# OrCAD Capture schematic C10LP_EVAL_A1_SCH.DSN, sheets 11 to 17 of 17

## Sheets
11 11. Ethernet: size B
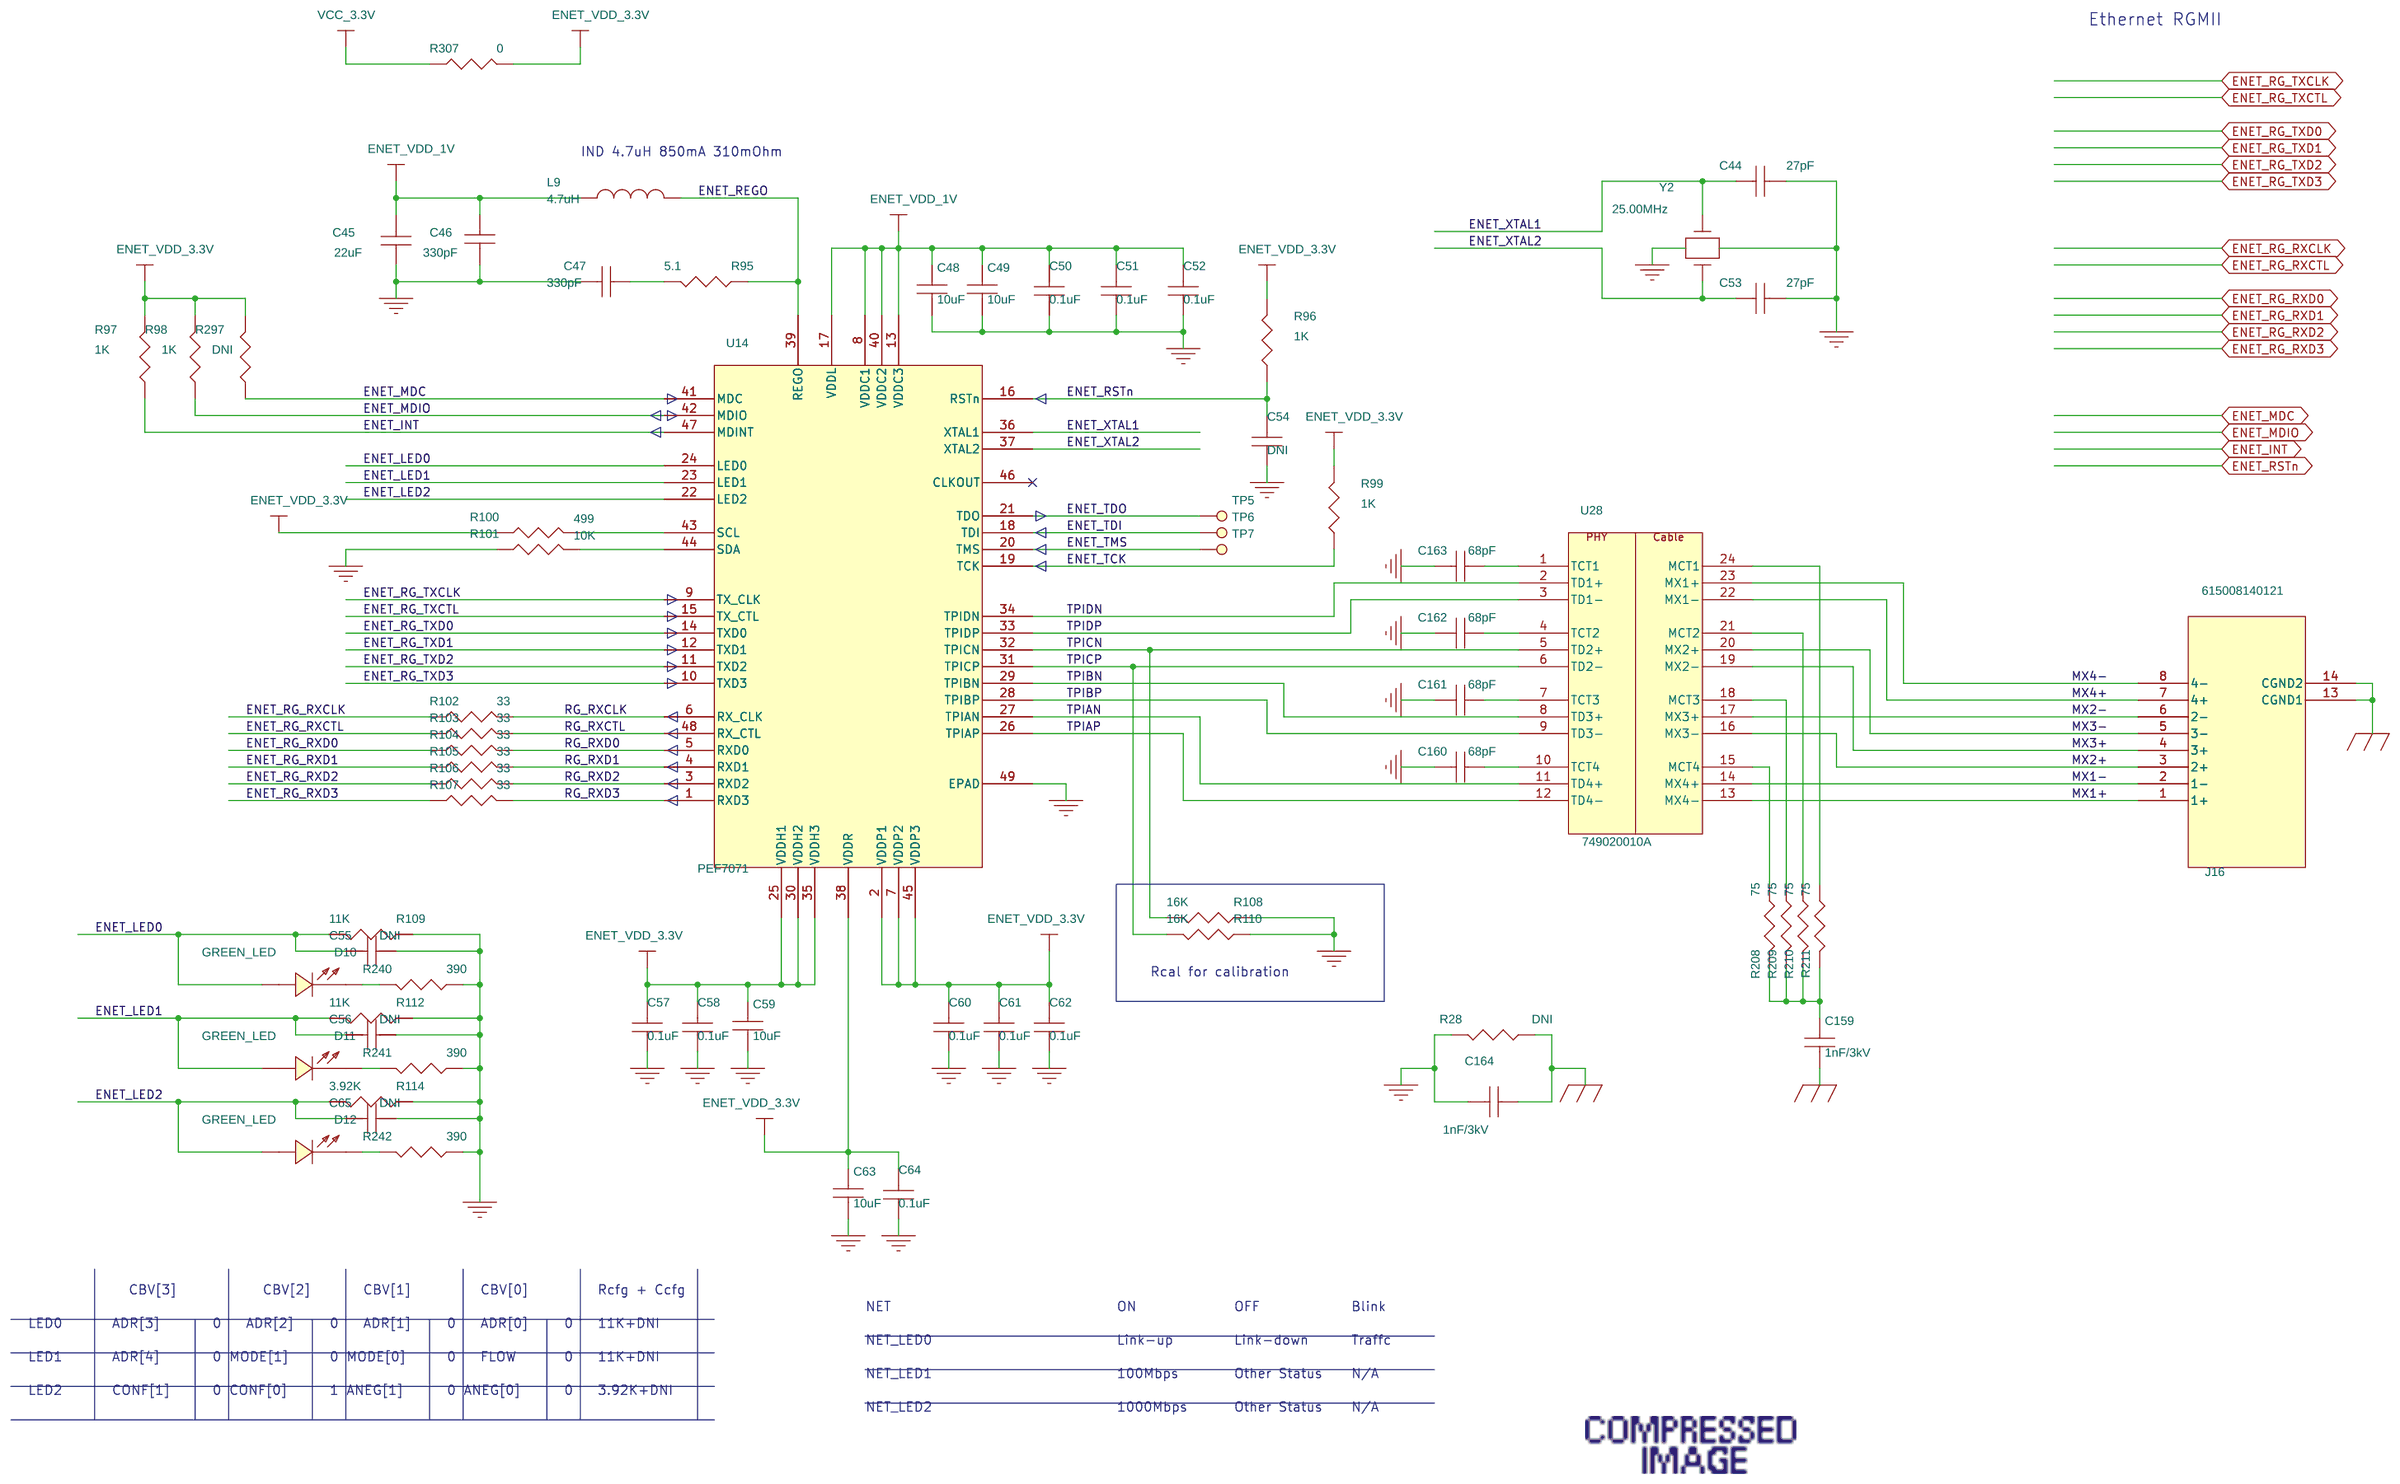
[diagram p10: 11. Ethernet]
12 12. Arduino Header: size B
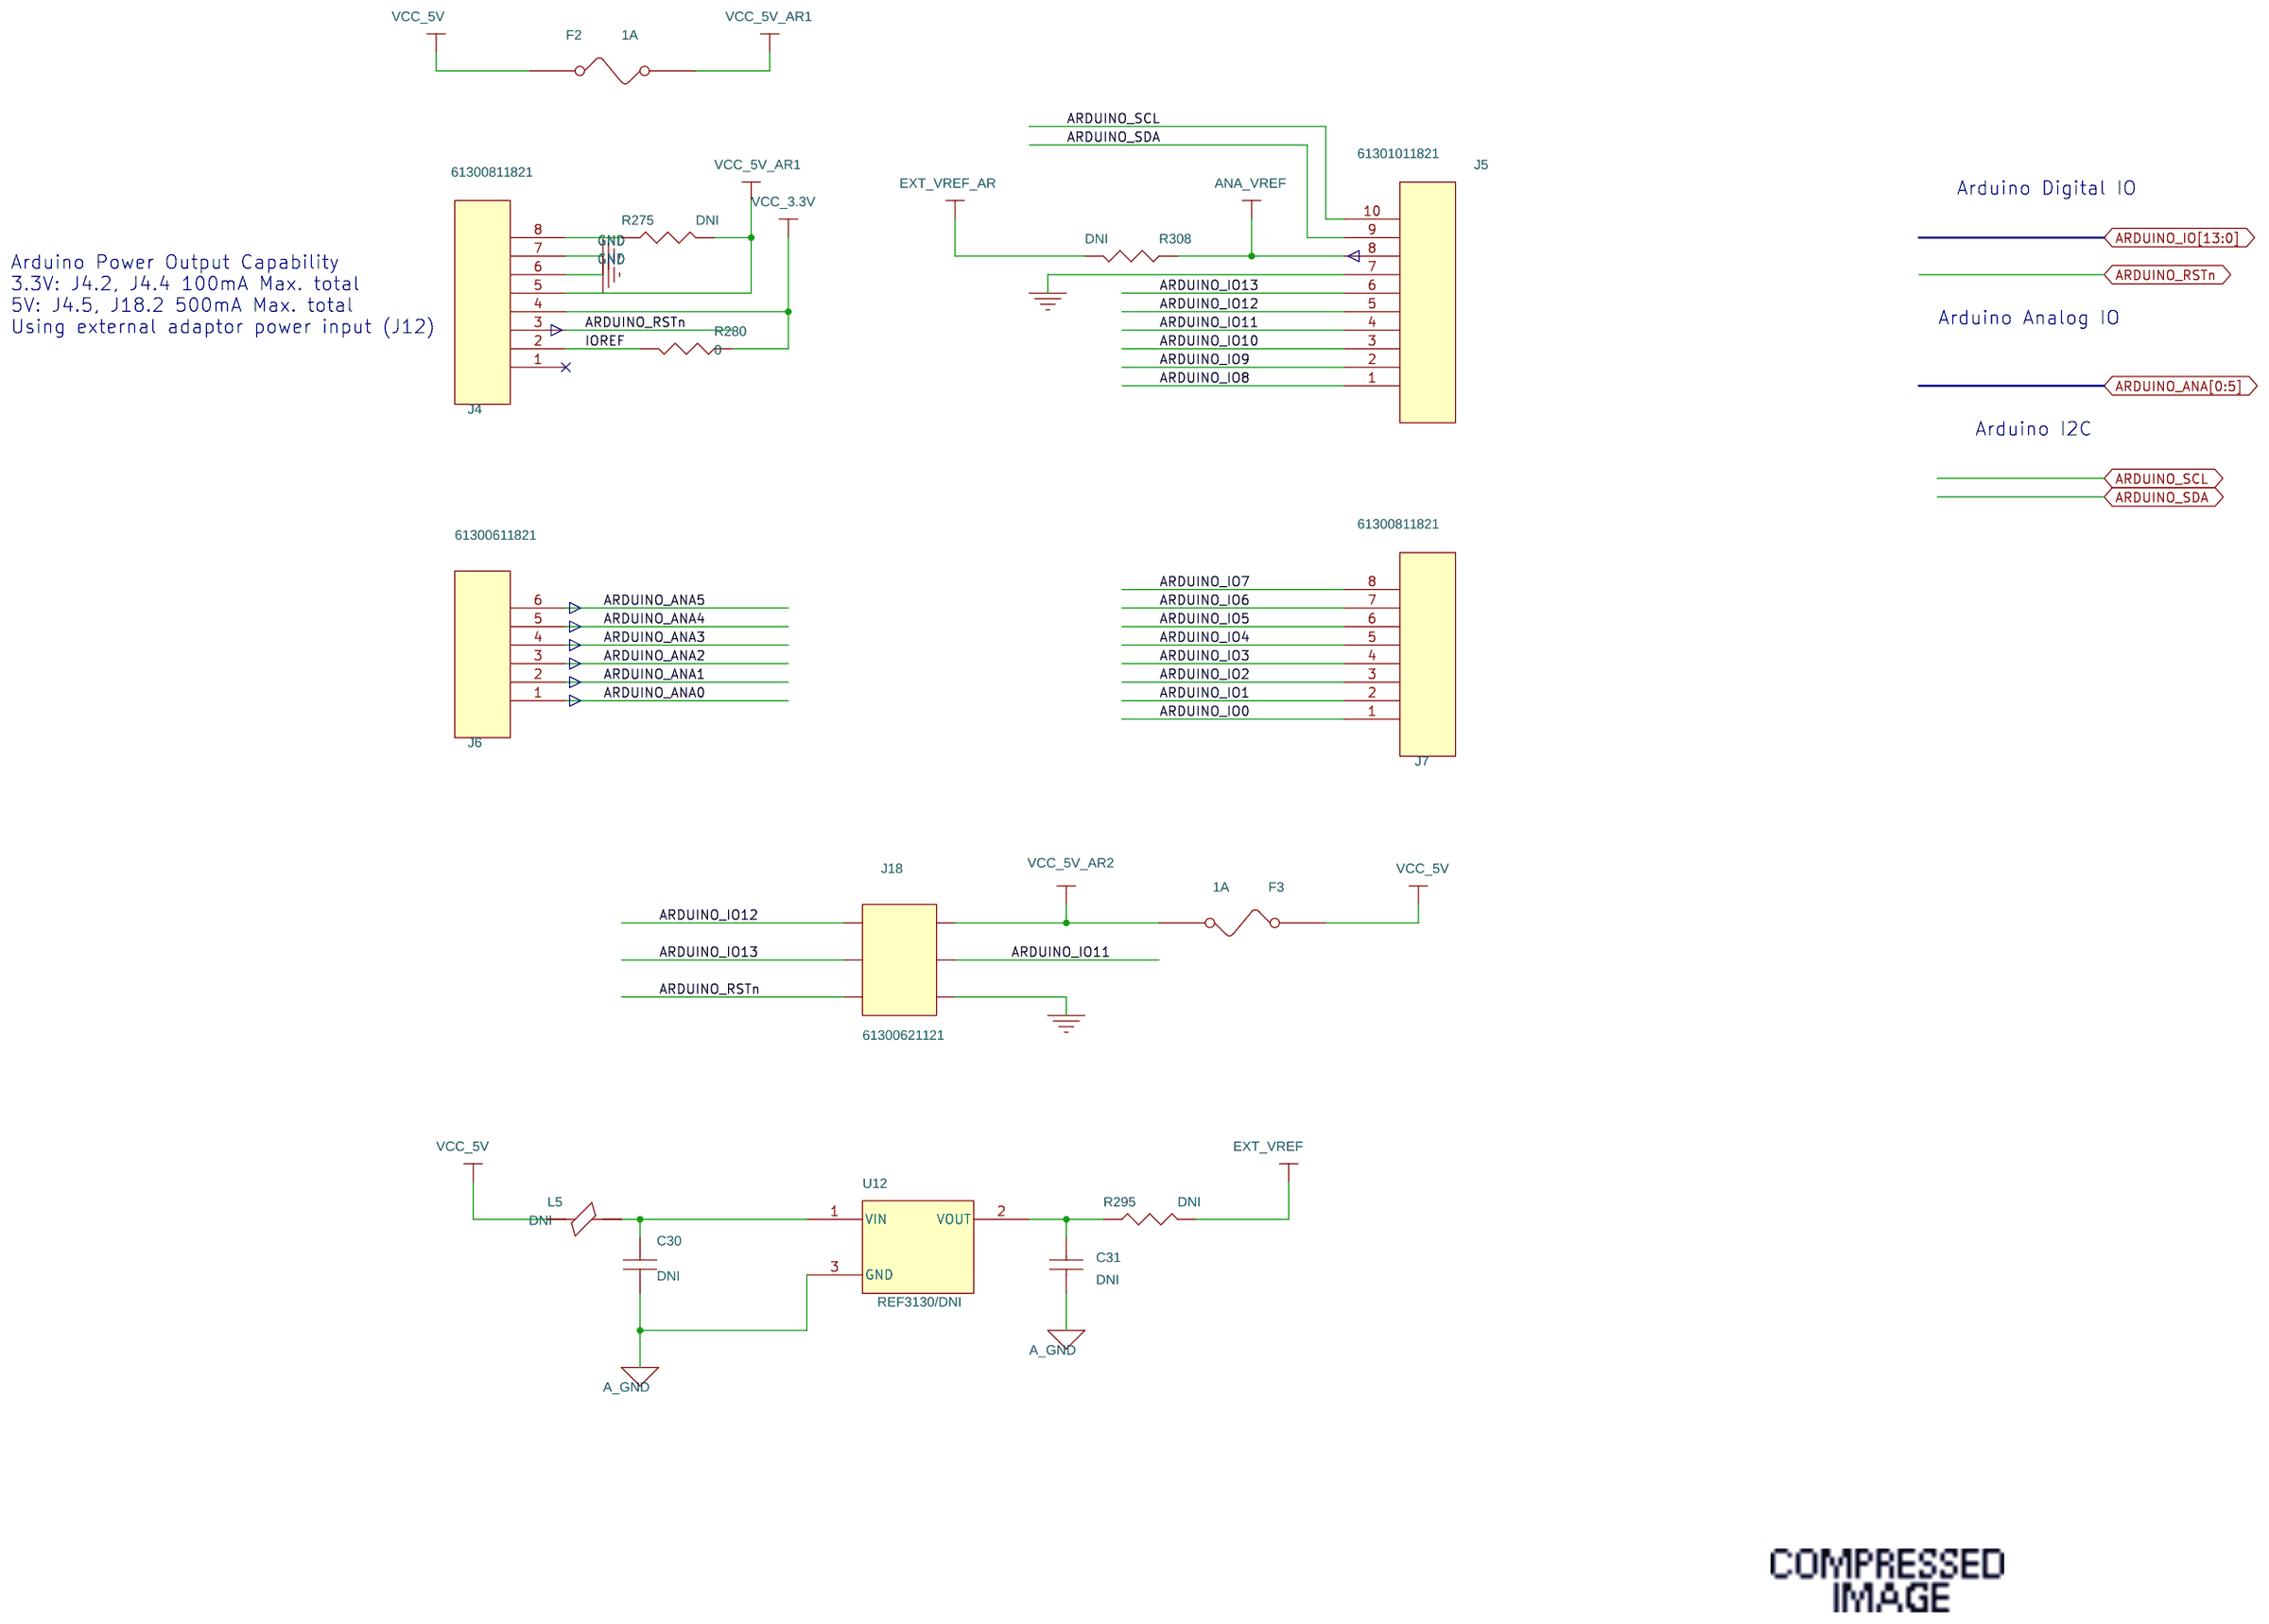
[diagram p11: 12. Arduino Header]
13 13. PMOD, 2x20 GPIO: size B
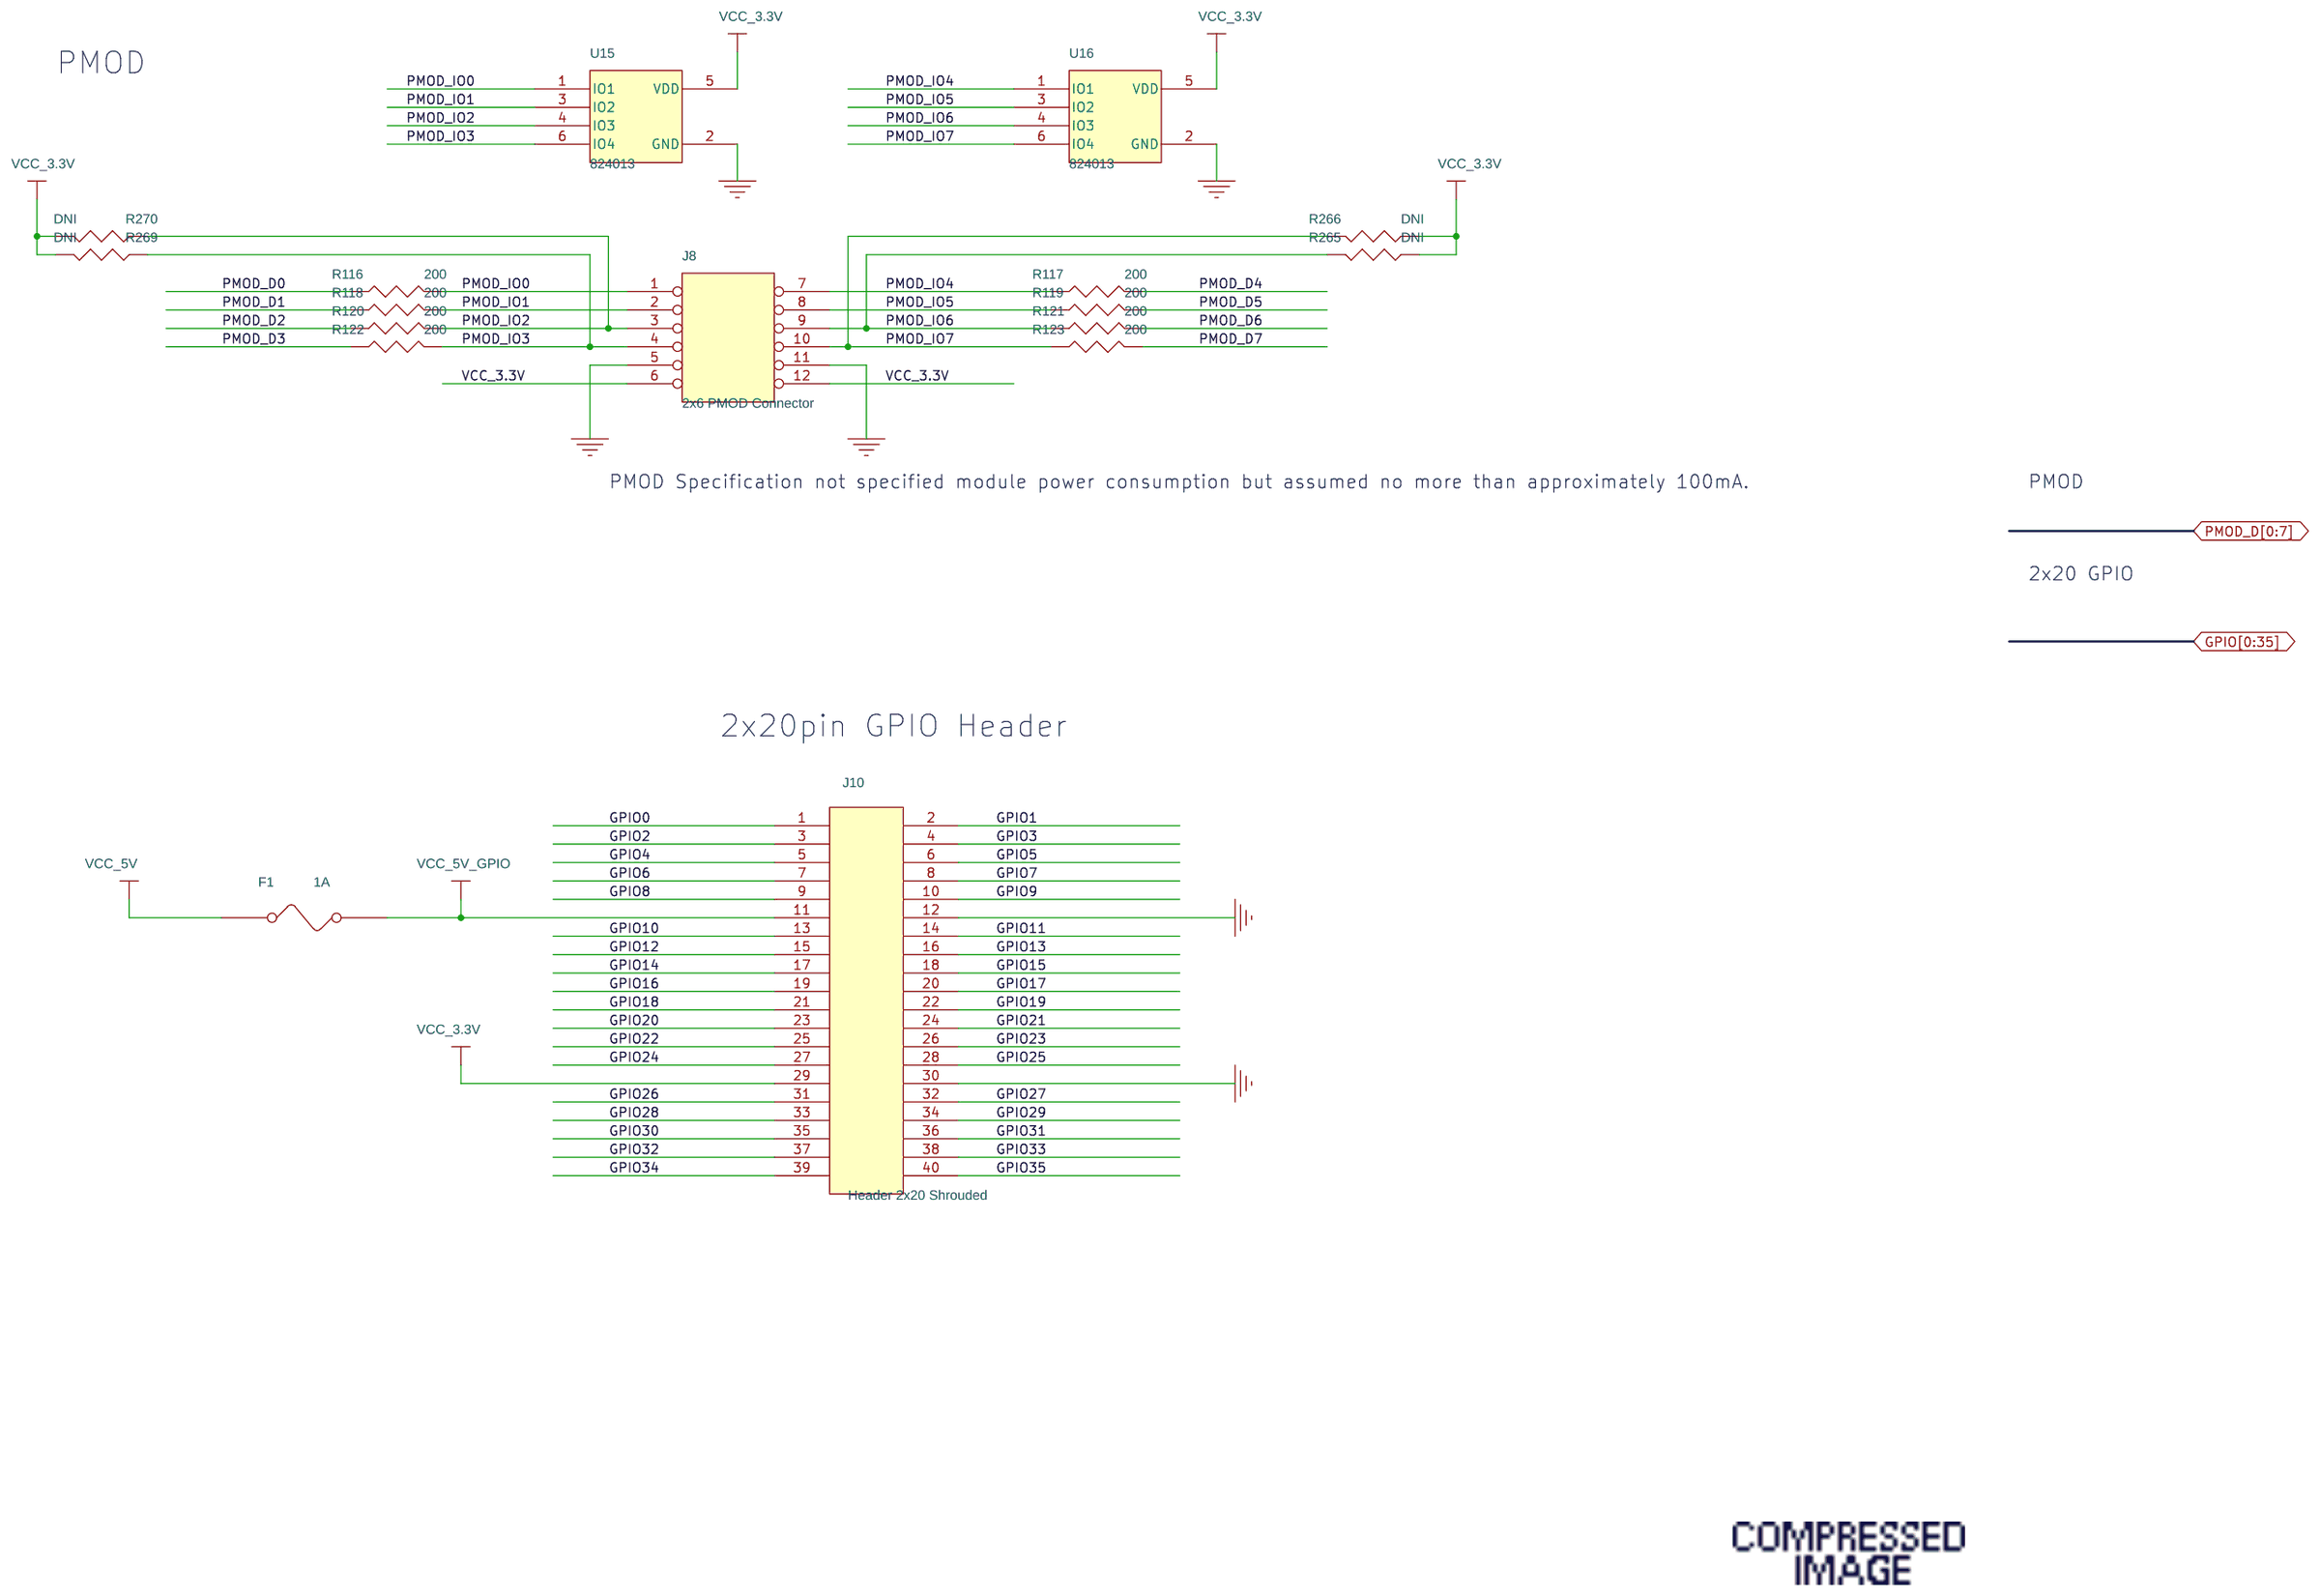
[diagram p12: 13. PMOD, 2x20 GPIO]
14 14. LED, PB, DIP SW: size B
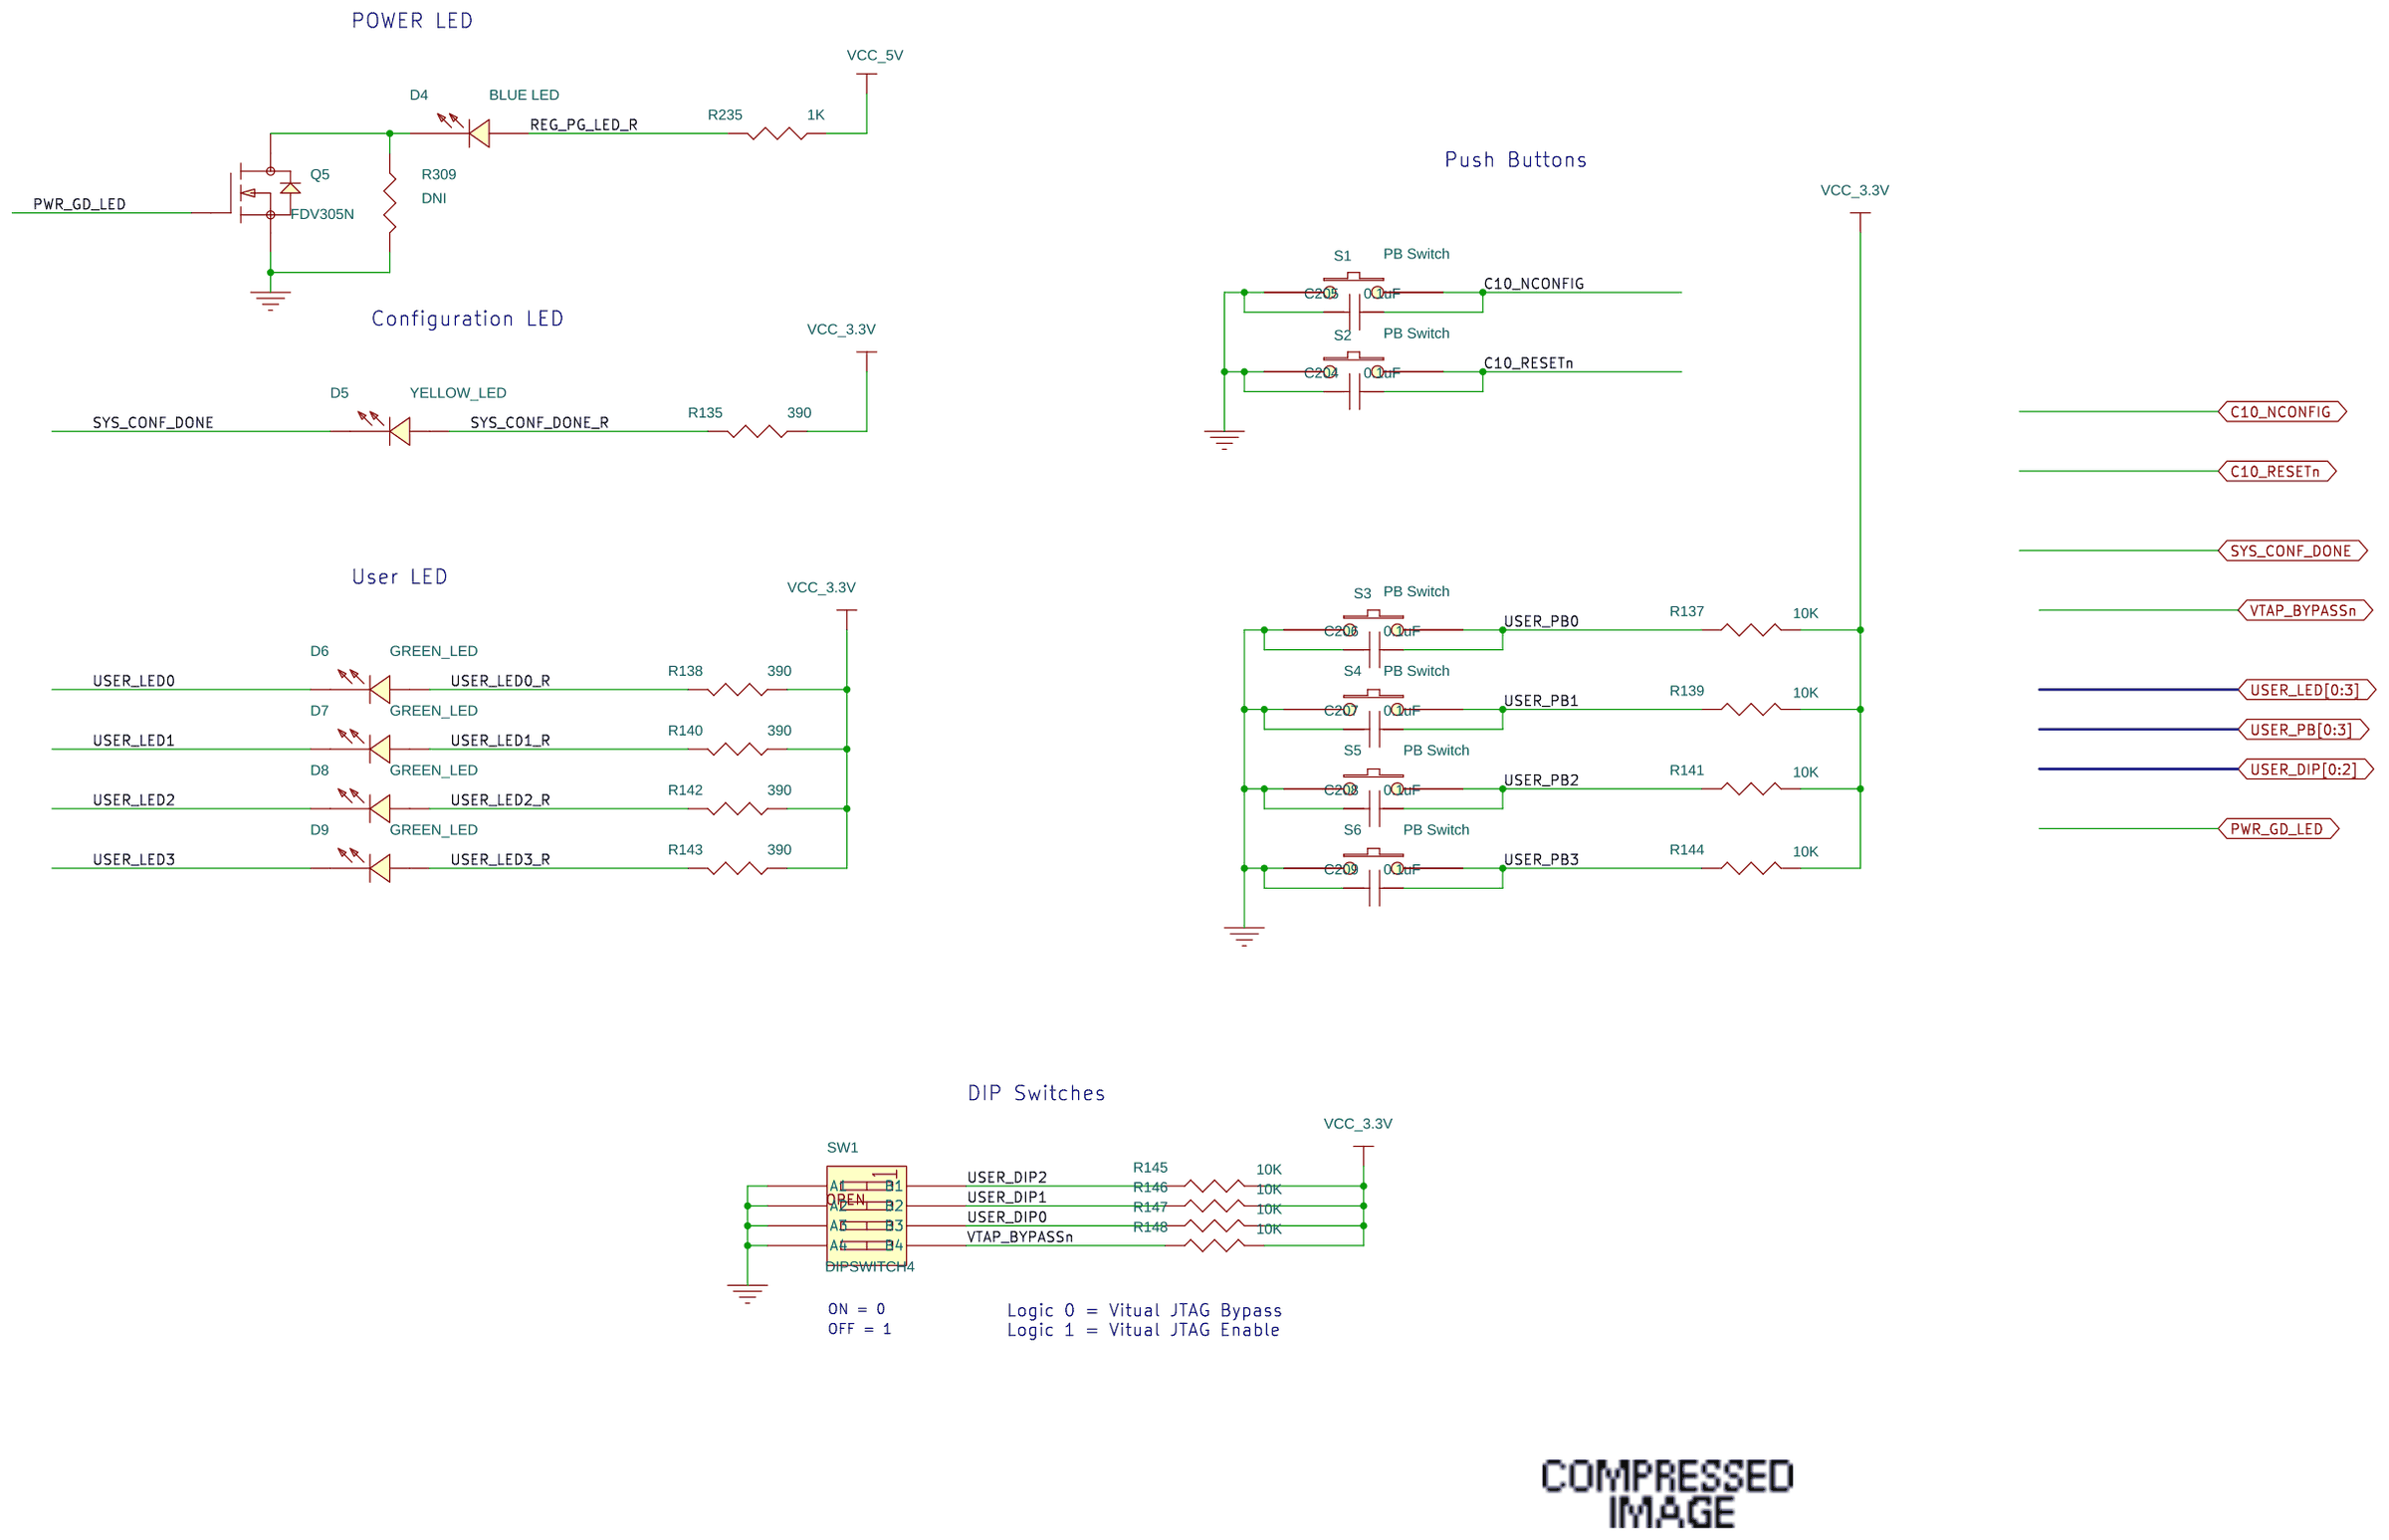
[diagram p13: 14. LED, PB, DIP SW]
15 15. Clock: size B
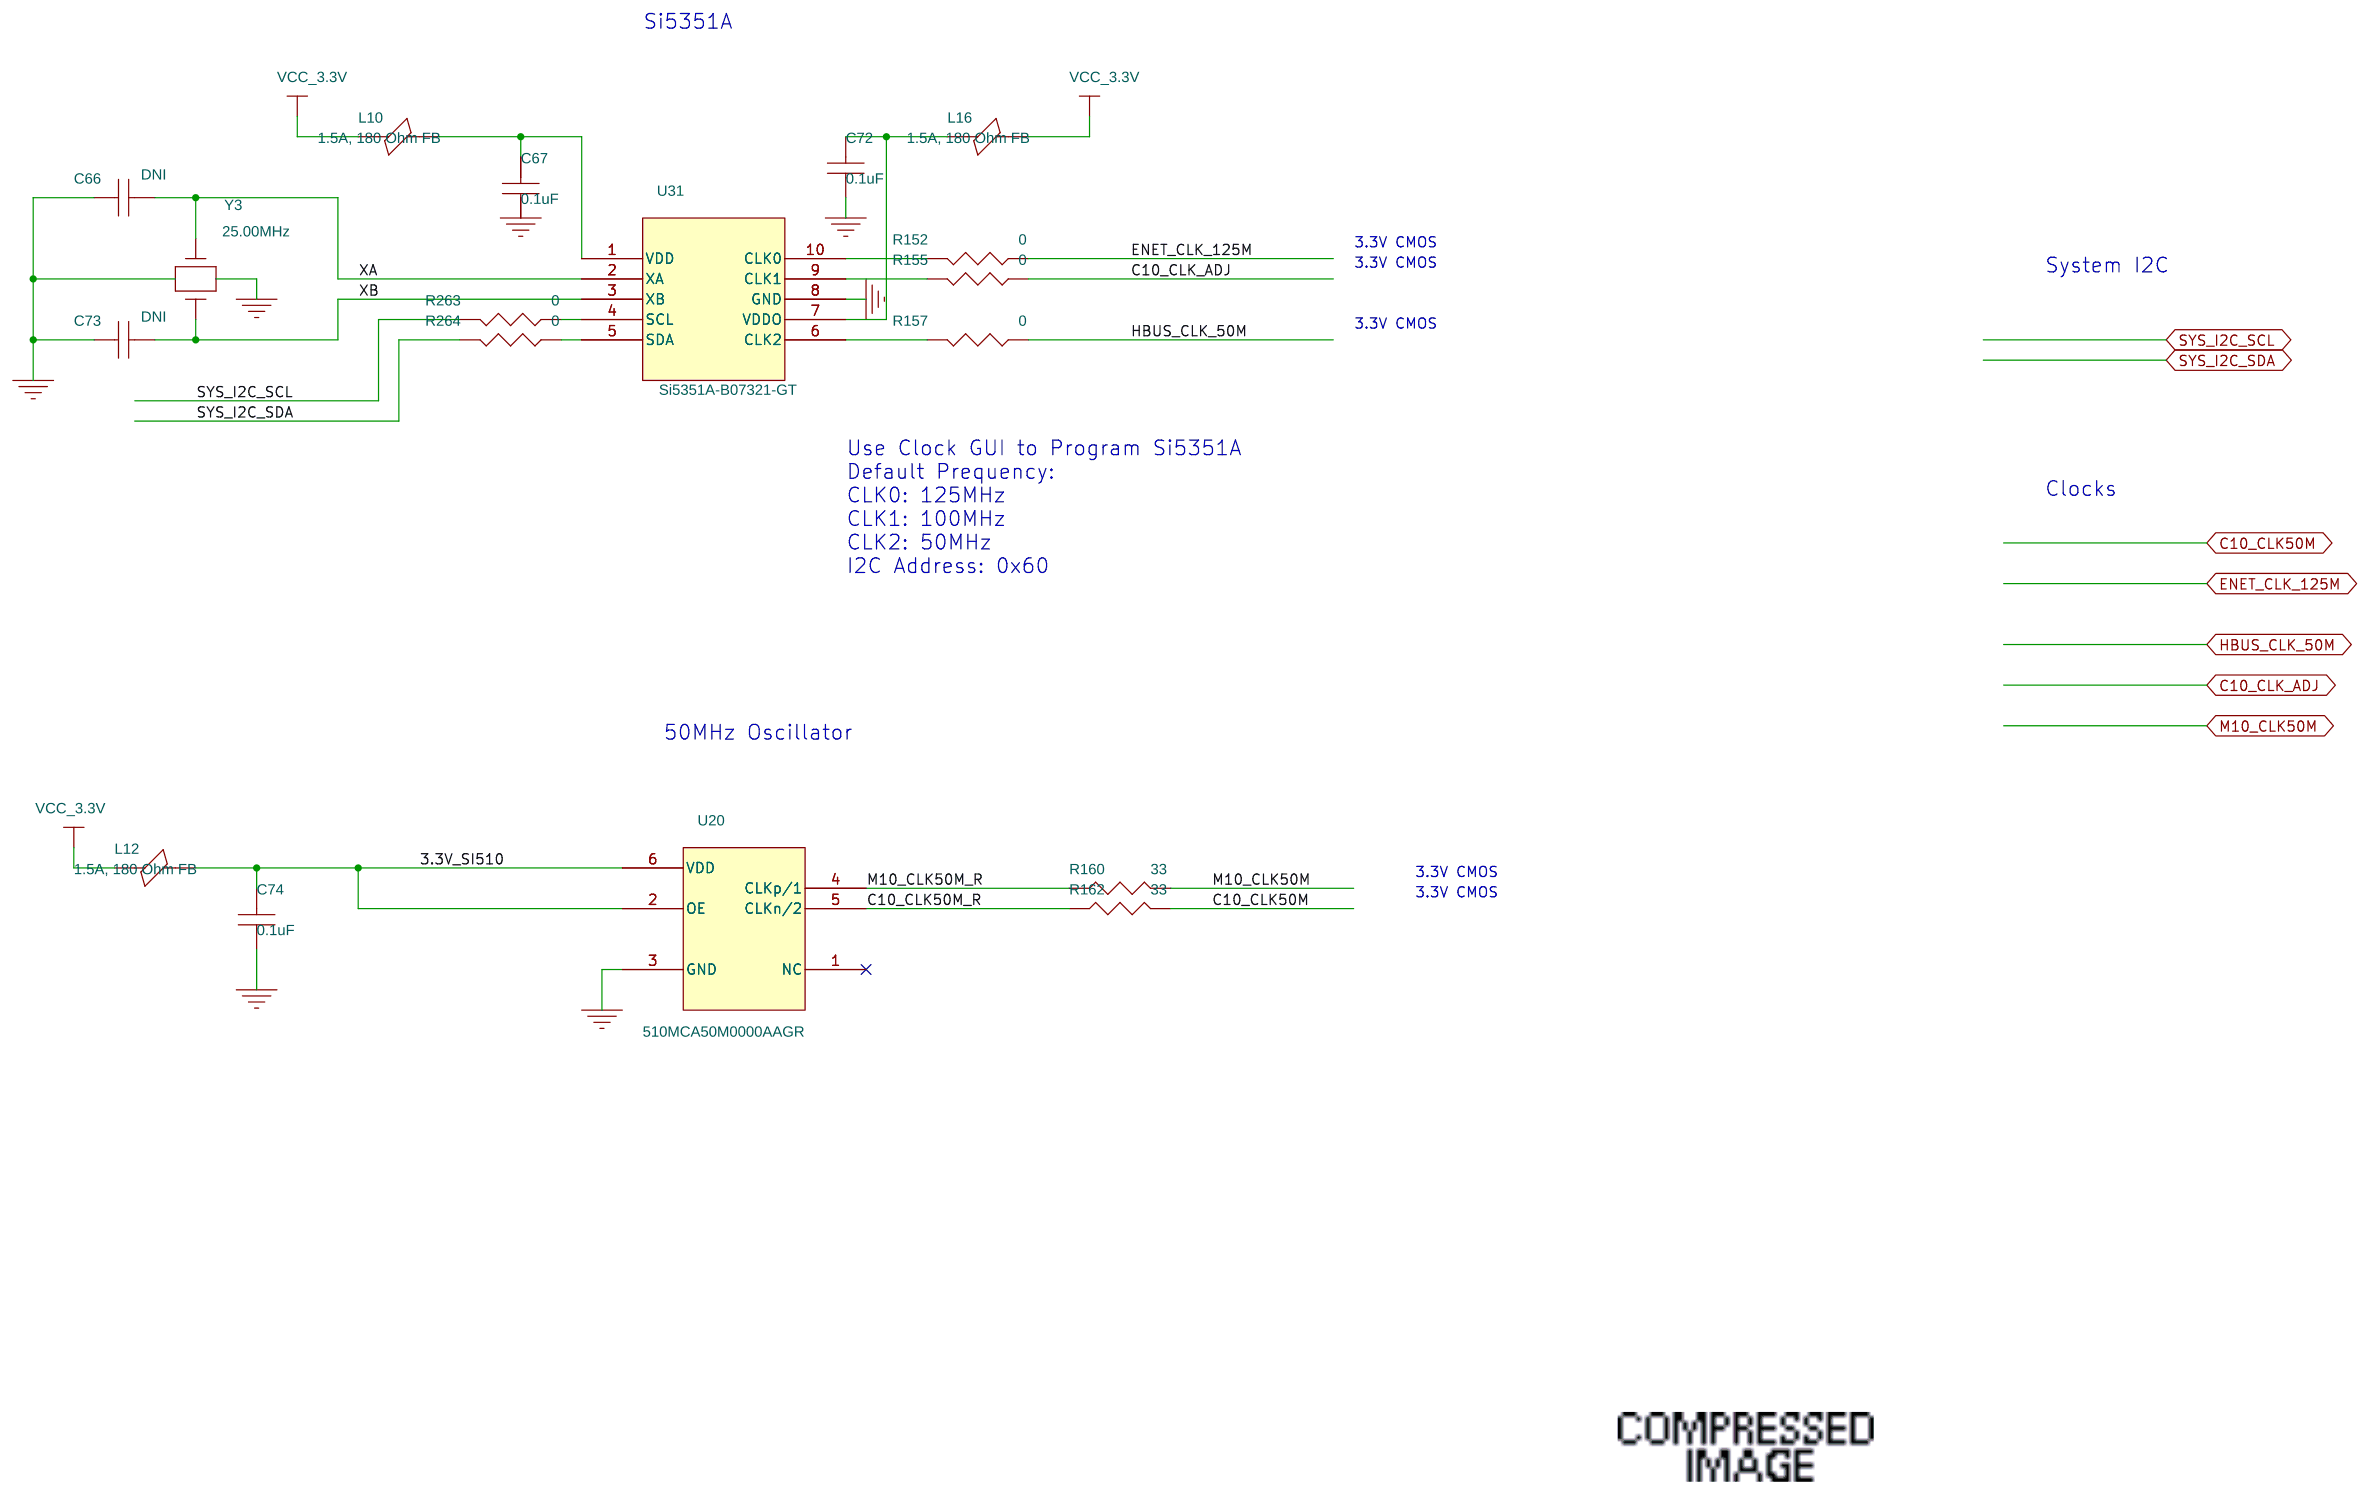
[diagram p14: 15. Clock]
16 16. Power Input: size B
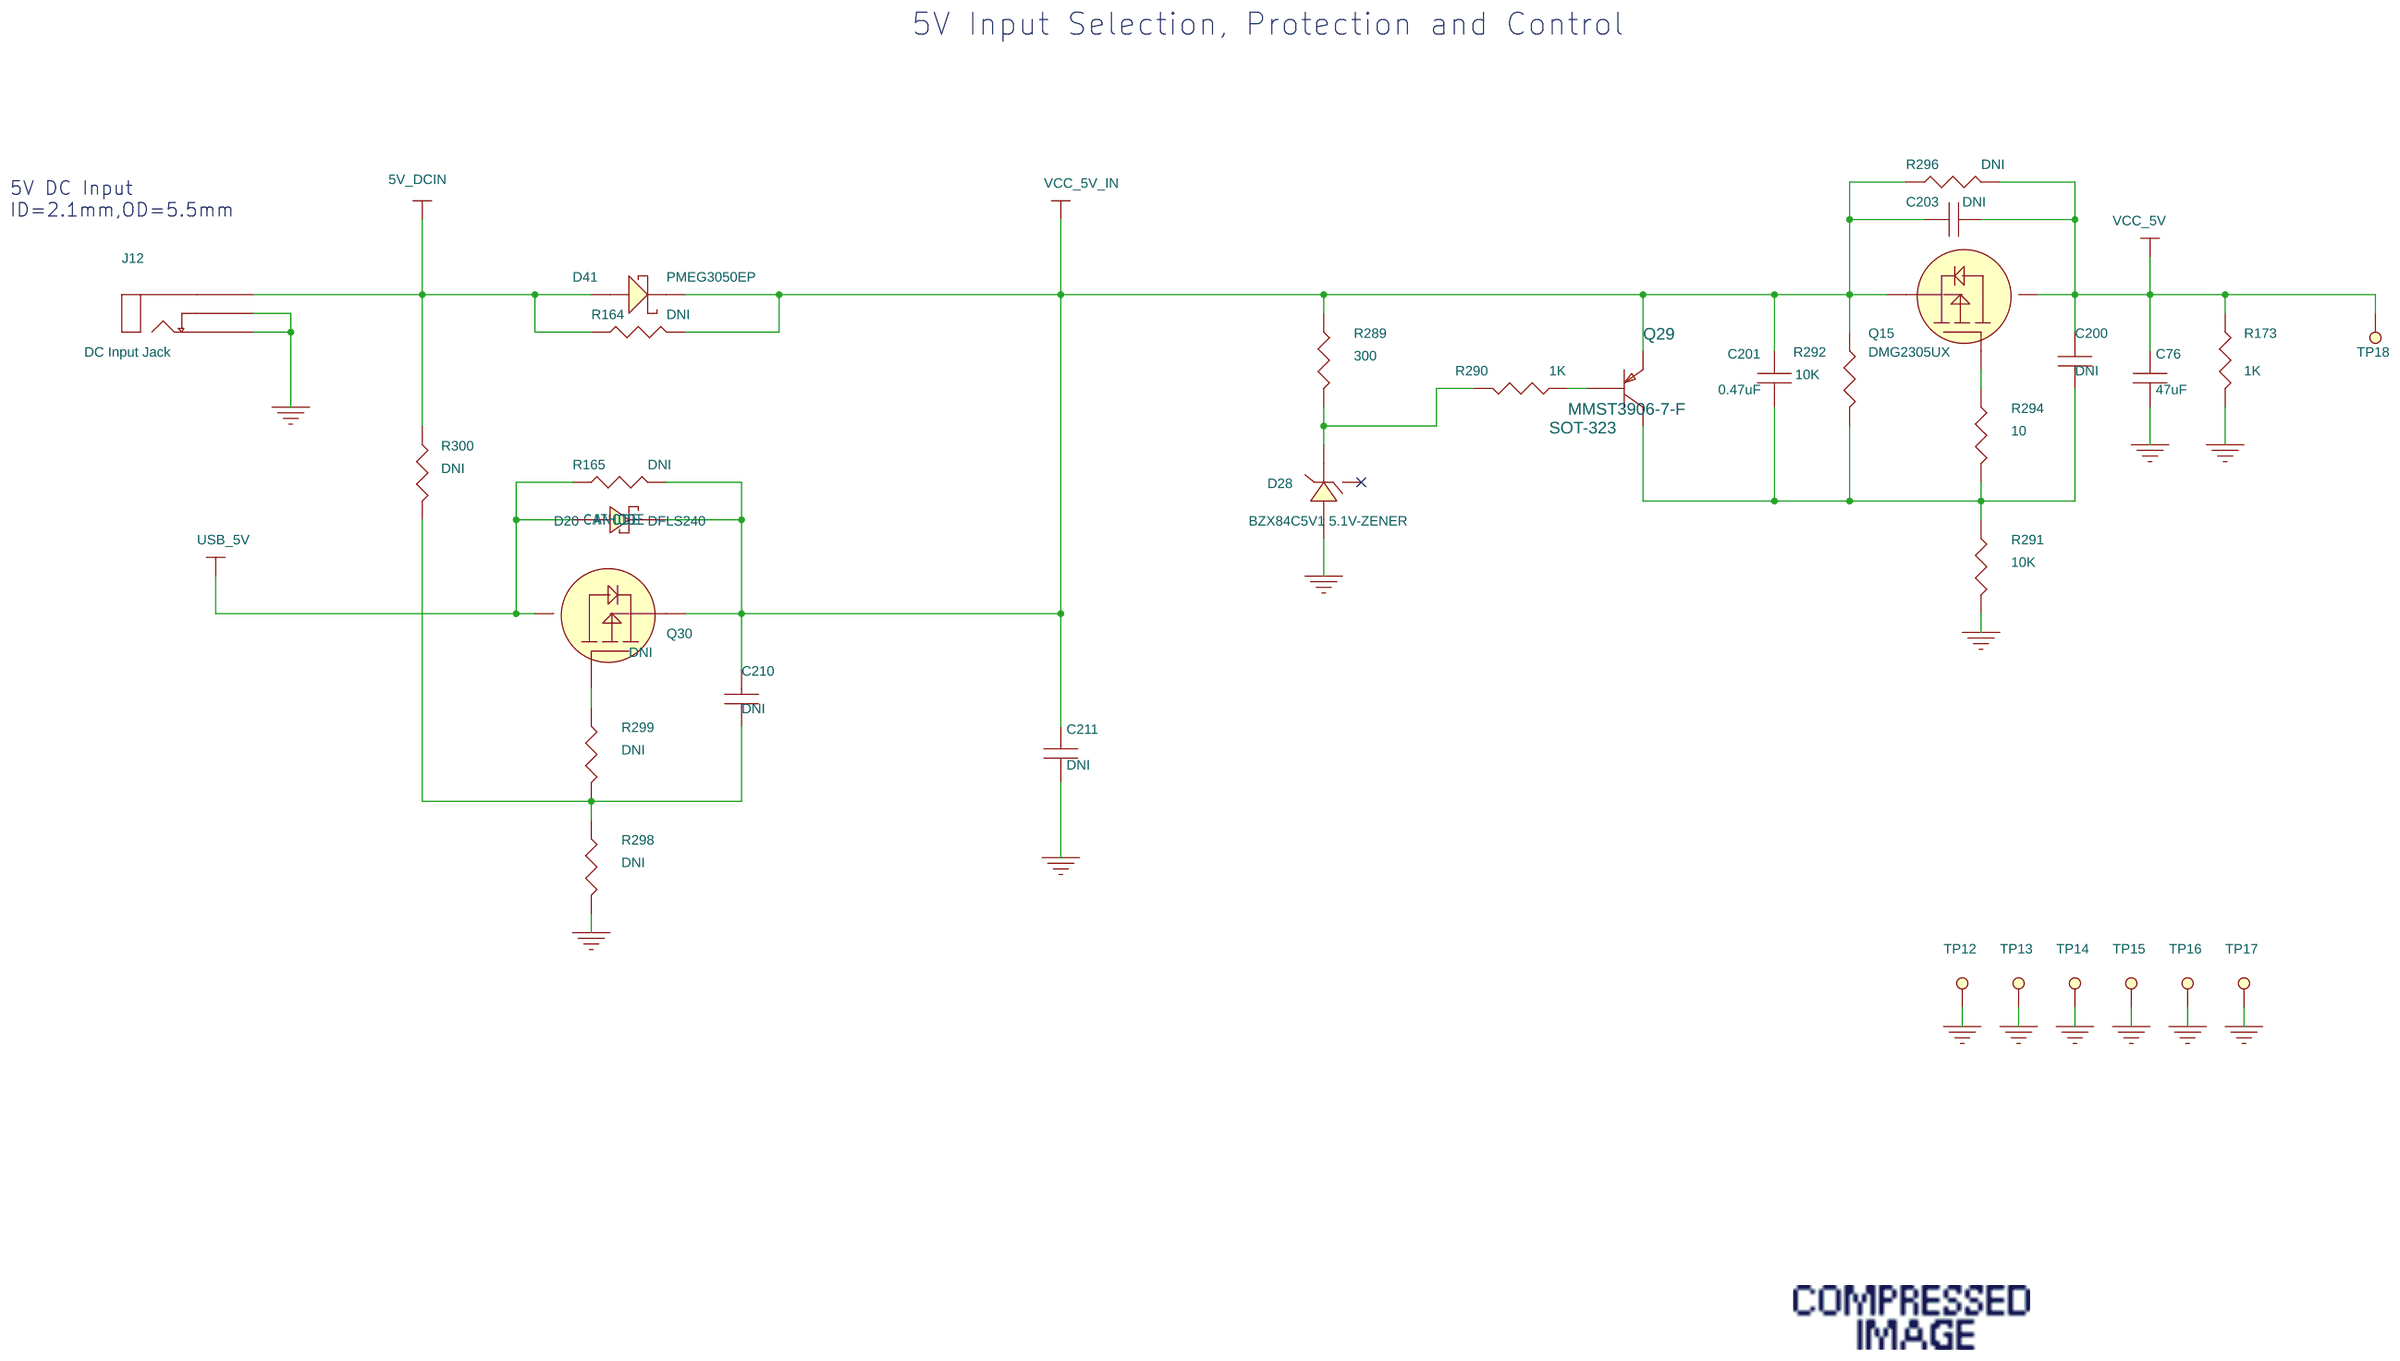
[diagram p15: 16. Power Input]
17 17. 1.2V, 1.8V, 2.5V, 3.3V: size B
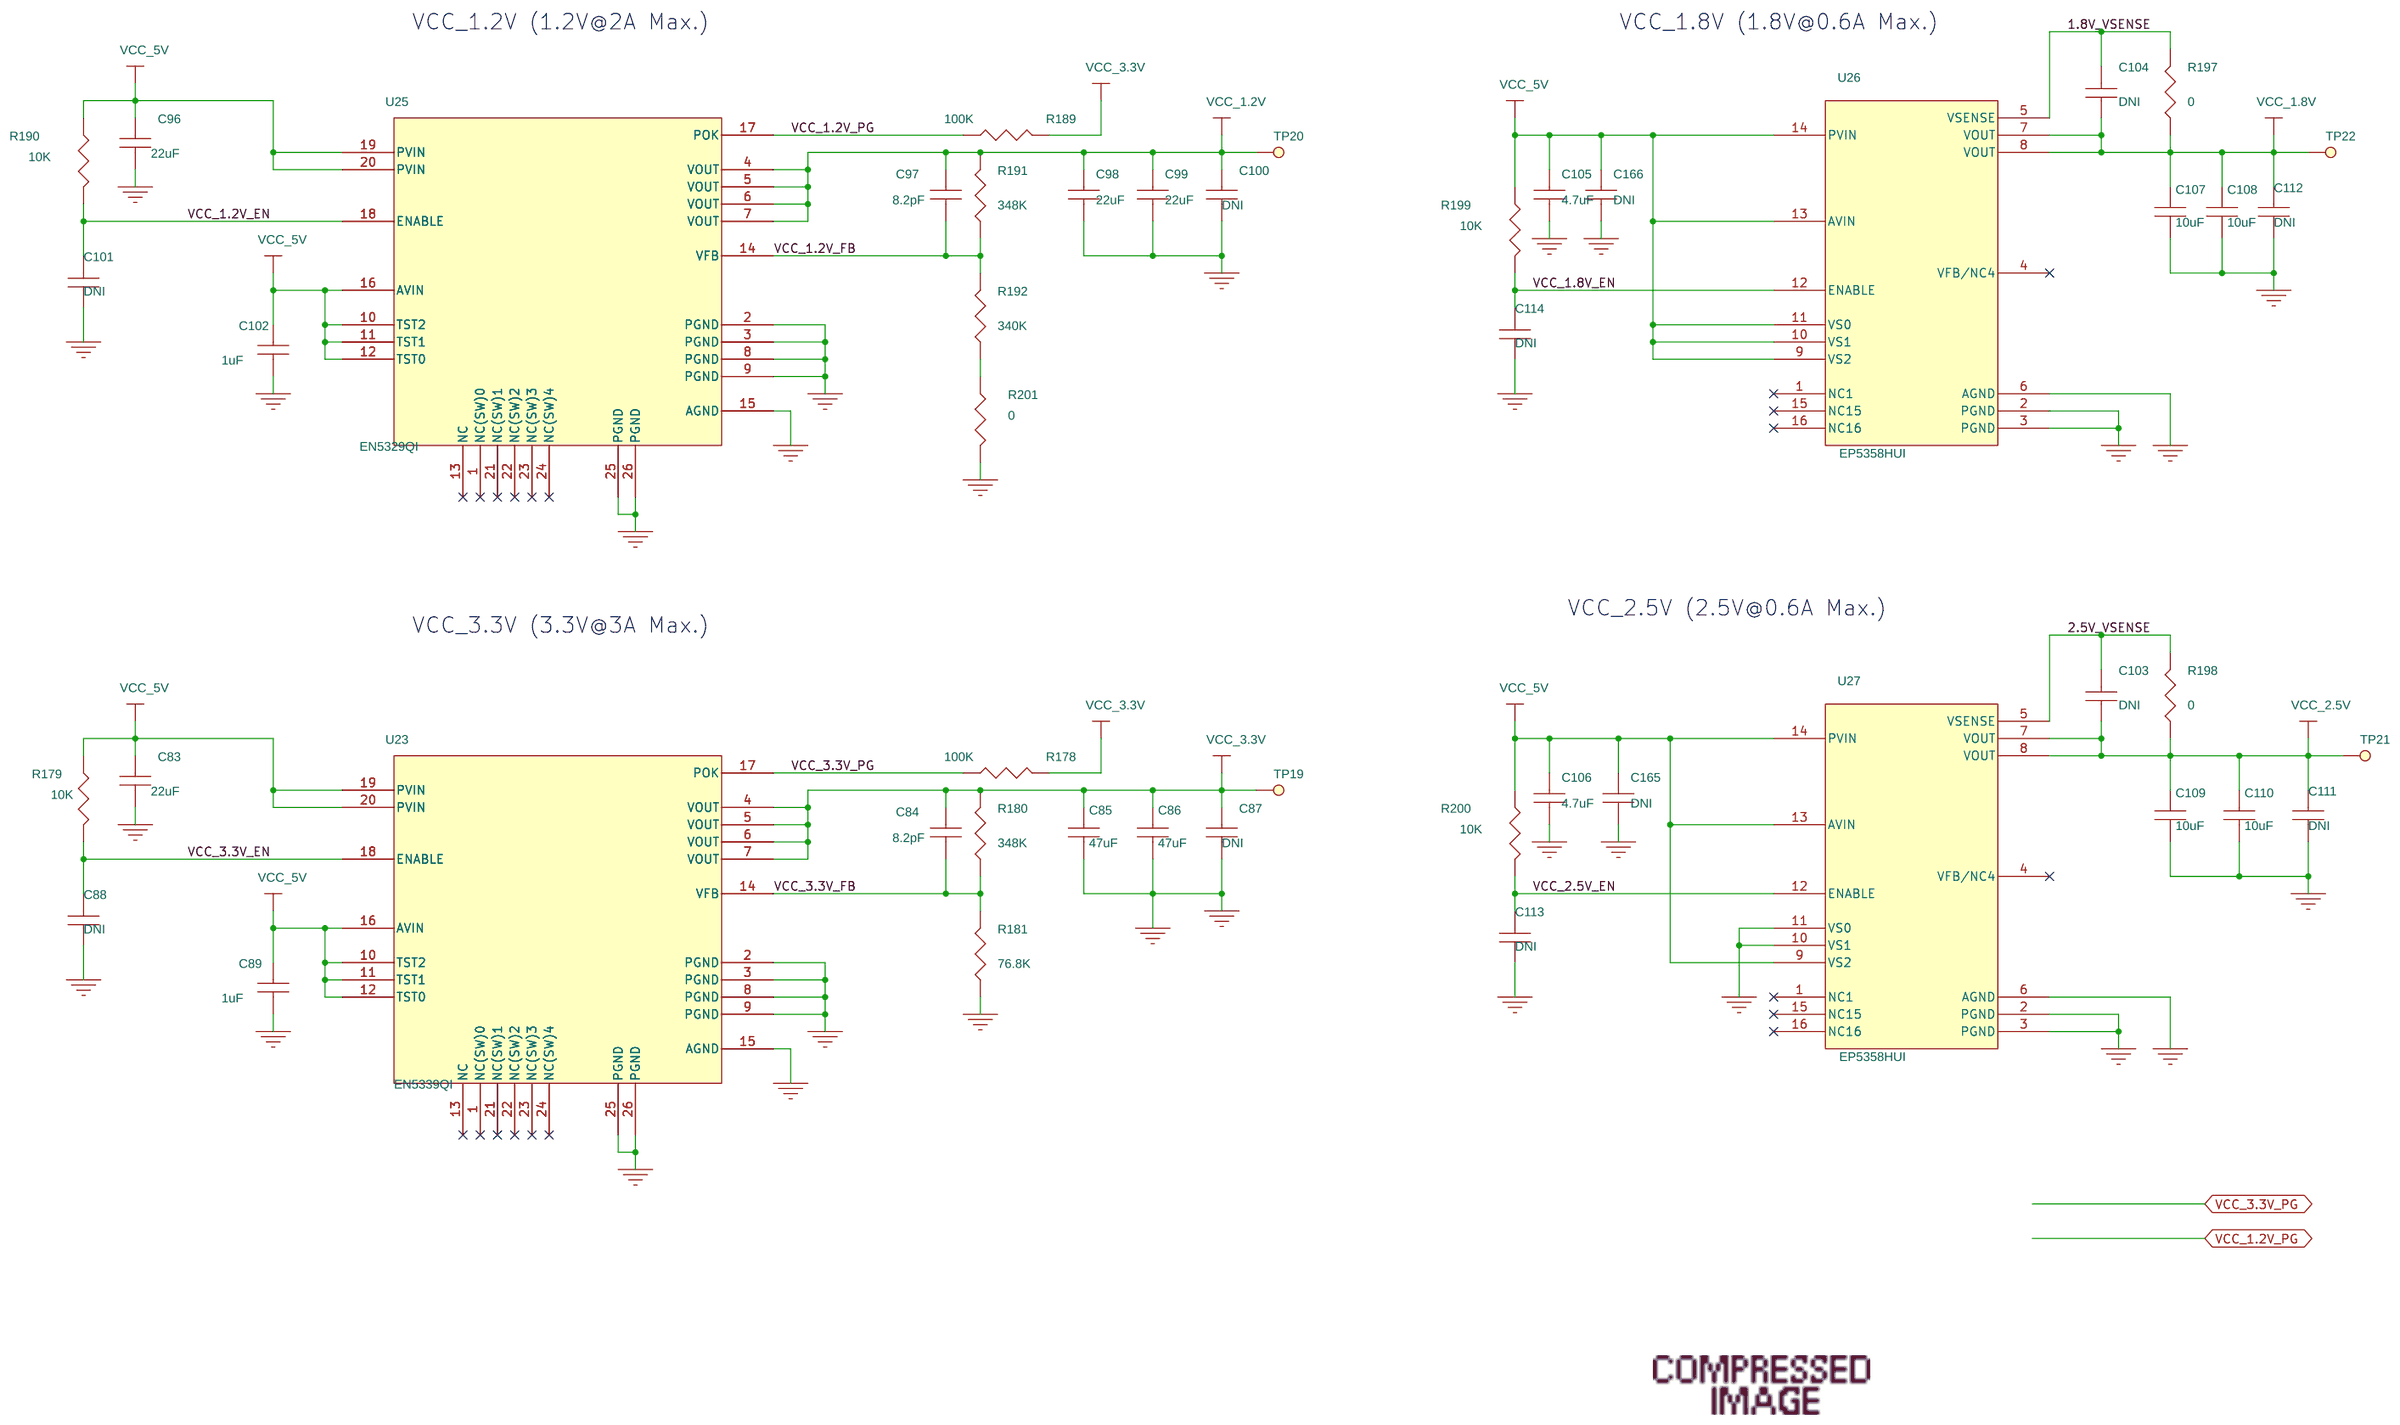
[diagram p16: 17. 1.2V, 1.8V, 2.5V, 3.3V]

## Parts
sheet 11. Ethernet
C44  27pF  [0402]
C45  22uF  [0805]
C46  330pF  [0402]
C47  330pF  [0402]
C48  10uF  [0603]
C49  10uF  [0603]
C50  0.1uF  [0402]
C51  0.1uF  [0402]
C52  0.1uF  [0402]
C53  27pF  [0402]
C54  DNI  [0402]
C55  DNI  [0402]
C56  DNI  [0402]
C57  0.1uF  [0402]
C58  0.1uF  [0402]
C59  10uF  [0603]
C60  0.1uF  [0402]
C61  0.1uF  [0402]
C62  0.1uF  [0402]
C63  10uF  [0603]
C64  0.1uF  [0402]
C65  DNI  [0402]
C159  1nF/3kV  [1808]
C160  68pF  [0402]
C161  68pF  [0402]
C162  68pF  [0402]
C163  68pF  [0402]
C164  1nF/3kV  [1808]
D10  GREEN_LED  [LED_0603]
D11  GREEN_LED  [LED_0603]
D12  GREEN_LED  [LED_0603]
J16  615008140121  [RJ45_615008140121]
L9  4.7uH  [IND_744028004]
R28  DNI  [1206]
R95  5.1  [0402]
R96  1K  [0402]
R97  1K  [0402]
R98  1K  [0402]
R99  1K  [0402]
R100  499  [0402]
R101  10K  [0402]
R102  33  [0402]
R103  33  [0402]
R104  33  [0402]
R105  33  [0402]
R106  33  [0402]
R107  33  [0402]
R108  16K  [0402]
R109  11K  [0402]
R110  16K  [0402]
R112  11K  [0402]
R114  3.92K  [0402]
R208  75  [0603]
R209  75  [0603]
R210  75  [0603]
R211  75  [0603]
R240  390  [0402]
R241  390  [0402]
R242  390  [0402]
R297  DNI  [0402]
R307  0  [0603]
TP5  VIA_1  [TP_020RD_SMT]
TP6  VIA_1  [TP_020RD_SMT]
TP7  VIA_1  [TP_020RD_SMT]
U14  PEF7071  [VQFN-48_PEF7071]
U28  749020010A  [LAN_XFMR_749020010A]
Y2  25.00MHz  [XTAL_FA-128]
sheet 12. Arduino Header
C30  DNI  [0402]
C31  DNI  [0402]
F2  1A  [0805]
F3  1A  [0805]
J4  61300811821  [HDR_1X8_100MIL]
J5  61301011821  [HDR_1X10_100MIL]
J6  61300611821  [HDR_1X6_100MIL]
J7  61300811821  [HDR_1X8_100MIL]
J18  61300621121  [HDR_2X3_100MIL_TH]
L5  DNI  [ind_0603]
R275  DNI  [0603]
R280  0  [0402]
R295  DNI  [0402]
R308  DNI  [0402]
U12  REF3130/DNI  [SOT23-3]
sheet 13. PMOD, 2x20 GPIO
F1  1A  [0805]
J8  2x6 PMOD Connector  [HDR2X6_100MIL]
J10  Header 2x20 Shrouded  [HDR_2x20_100mil_TH_SR]
R116  200  [0402]
R117  200  [0402]
R118  200  [0402]
R119  200  [0402]
R120  200  [0402]
R121  200  [0402]
R122  200  [0402]
R123  200  [0402]
R265  DNI  [0402]
R266  DNI  [0402]
R269  DNI  [0402]
R270  DNI  [0402]
U15  824013  [SOT23-6L]
U16  824013  [SOT23-6L]
sheet 14. LED, PB, DIP SW
C204  0.1uF  [0402]
C205  0.1uF  [0402]
C206  0.1uF  [0402]
C207  0.1uF  [0402]
C208  0.1uF  [0402]
C209  0.1uF  [0402]
D4  BLUE LED  [LED_0603]
D5  YELLOW_LED  [LED_0603]
D6  GREEN_LED  [LED_0603]
D7  GREEN_LED  [LED_0603]
D8  GREEN_LED  [LED_0603]
D9  GREEN_LED  [LED_0603]
Q5  FDV305N  [SOT23]
R135  390  [0402]
R137  10K  [0402]
R138  390  [0402]
R139  10K  [0402]
R140  390  [0402]
R141  10K  [0402]
R142  390  [0402]
R143  390  [0402]
R144  10K  [0402]
R145  10K  [0402]
R146  10K  [0402]
R147  10K  [0402]
R148  10K  [0402]
R235  1K  [0402]
R309  DNI  [0402]
S1  PB Switch  [WURTH_6X3P5_TACT_SWITCH]
S2  PB Switch  [WURTH_6X3P5_TACT_SWITCH]
S3  PB Switch  [WURTH_6X3P5_TACT_SWITCH]
S4  PB Switch  [WURTH_6X3P5_TACT_SWITCH]
S5  PB Switch  [WURTH_6X3P5_TACT_SWITCH]
S6  PB Switch  [WURTH_6X3P5_TACT_SWITCH]
SW1  DIPSWITCH4  [DIPSWITCH_SMT_QUAD]
sheet 15. Clock
C66  DNI  [0402]
C67  0.1uF  [0402]
C72  0.1uF  [0402]
C73  DNI  [0402]
C74  0.1uF  [0402]
L10  1.5A, 180 Ohm FB  [ind_0603]
L12  1.5A, 180 Ohm FB  [ind_0603]
L16  1.5A, 180 Ohm FB  [ind_0603]
R152  0  [0402]
R155  0  [0402]
R157  0  [0402]
R160  33  [0402]
R162  33  [0402]
R263  0  [0402]
R264  0  [0402]
U20  510MCA50M0000AAGR  [si510]
U31  Si5351A-B07321-GT  [MSOP-10_Si5351]
Y3  25.00MHz  [XTAL_FA-238]
sheet 16. Power Input
C76  47uF  [0805]
C200  DNI  [0402]
C201  0.47uF  [0603]
C203  DNI  [0402]
C210  DNI  [0402]
C211  DNI  [0805]
D20  DFLS240  [POWERDI123]
D28  BZX84C5V1 5.1V-ZENER  [SOT-23_BZX84]
D41  PMEG3050EP  [SOD128_CFP5]
J12  DC Input Jack  [JACK-DC_2MM_WE]
Q15  DMG2305UX  [SOT-23]
Q29  MMST3906-7-F  [SOT-323]
Q30  DNI  [SOT-23]
R164  DNI  [0805]
R165  DNI  [0805]
R173  1K  [0805]
R289  300  [0402]
R290  1K  [0402]
R291  10K  [0402]
R292  10K  [0402]
R294  10  [0402]
R296  DNI  [0805]
R298  DNI  [0402]
R299  DNI  [0402]
R300  DNI  [0402]
TP12  VIA_1  [TP_040RD_SMT]
TP13  VIA_1  [TP_040RD_SMT]
TP14  VIA_1  [TP_040RD_SMT]
TP15  VIA_1  [TP_040RD_SMT]
TP16  VIA_1  [TP_040RD_SMT]
TP17  VIA_1  [TP_040RD_SMT]
TP18  VIA_1  [TP_040RD_SMT]
sheet 17. 1.2V, 1.8V, 2.5V, 3.3V
C83  22uF  [0805]
C84  8.2pF  [0402]
C85  47uF  [0805]
C86  47uF  [0805]
C87  DNI  [0402]
C88  DNI  [0402]
C89  1uF  [0402]
C96  22uF  [0805]
C97  8.2pF  [0402]
C98  22uF  [0805]
C99  22uF  [0805]
C100  DNI  [0402]
C101  DNI  [0402]
C102  1uF  [0402]
C103  DNI  [0402]
C104  DNI  [0402]
C105  4.7uF  [0603]
C106  4.7uF  [0603]
C107  10uF  [0805]
C108  10uF  [0805]
C109  10uF  [0805]
C110  10uF  [0805]
C111  DNI  [0402]
C112  DNI  [0402]
C113  DNI  [0402]
C114  DNI  [0402]
C165  DNI  [0603]
C166  DNI  [0603]
R178  100K  [0402]
R179  10K  [0402]
R180  348K  [0402]
R181  76.8K  [0402]
R189  100K  [0402]
R190  10K  [0402]
R191  348K  [0402]
R192  340K  [0402]
R197  0  [0402]
R198  0  [0402]
R199  10K  [0402]
R200  10K  [0402]
R201  0  [0402]
TP19  VIA_1  [TP_040RD_SMT]
TP20  VIA_1  [TP_040RD_SMT]
TP21  VIA_1  [TP_040RD_SMT]
TP22  VIA_1  [TP_040RD_SMT]
U23  EN5339QI  [EN5339QI]
U25  EN5329QI  [EN5339QI]
U26  EP5358HUI  [uQFN16]
U27  EP5358HUI  [uQFN16]

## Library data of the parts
C44 C53 = CAP: CAP, CERAMIC, 27PF, 1%, NPO, 50V, 0402; AGILE_LINK: http://sj-agile9app/Agile/PLMServlet?action=OpenEmailObject&classid=10000&objid=213459014; Item Num: P03-17658R; Lead Free Status: Lead Free; MFR_LIFECYCLE: Active; Manufacturer: Murata; Manufacturer Part Num: GRM1555C1H270FA01D; Num Pins: 2; PART_SUBCLASS: CAPACITORS; RoHS Compliant: Yes
C45 = CAP: CAP - CER, 22UF, 6.3V, +/-10%, X5R, 0805 SMD; CAPACITANCE: 10uF; Item Num: P03-16292R; LIFECYCLE_PHASE: Active; MFR_LIFECYCLE: Active; Manufacturer: Taiyo Yuden; Manufacturer Part Num: JMK212BJ226KG-T; PART_SUBCLASS: CAPACITORS; RATED_VOLTAGE: 6.3V
C46 C47 C203 = CAP: CAP CER 330PF 50V C0G/NP0 0402; Item Num: P03-17914R; Manufacturer: Murata; Manufacturer Part Num: GRM1555C1H331JA01D
C48 C49 C59 C63 = CAP: CAP - CER 10UF 6.3V 20% X5R 0603; Item Num: P03-15733R; Manufacturer: Murata; Manufacturer Part Num: GRM188R60J106ME47X; RoHS Compliant: RoHS Compliant
C50-C52 C57 C58 C60-C62 C64 C67 C72 C74 C204-C209 = CAP: CAP CER 0.1UF 25V 20% X7R 0402; Item Num: P03-17618R; Manufacturer: MURATA ELECTRONICS NORTH AMERICA; Manufacturer Part Num: GRM155R71E104KE14D; Num Pins: 2; Part Class: CAPACITORS; Price: 0; RoHS Compliant: RoHS Compliant
C31 C54-C56 C65 C88 C101 C113 C114 C200 C210 = CAP: CAP CER 0.1UF 25V 20% X7R 0402; CAPACITANCE: 0.1uF; Item Num: P03-17618R; Manufacturer: MURATA ELECTRONICS NORTH AMERICA; Manufacturer Part Num: GRM155R71E104KE14D; Num Pins: 2; Part Class: CAPACITORS; Price: 0; RoHS Compliant: RoHS Compliant
C159 C164 = CAP: CAP CER 1000PF 3KV X7R 1808; Item Num: P03-17908R; Manufacturer: Yageo; Manufacturer Part Num: CC1808KKX7REBB102
C160-C163 = CAP: CAP,CER,68PF,0402,5%,50VDC,NP0; Item Num: P03-11353R; Manufacturer: Murata; Manufacturer Part Num: GRM1555C1H680JA01D; RoHS Compliant: RoHS Compliant
D6-D12 = LED_WURTH_1: LED - BRIGHT GREEN, VF=2V, IF=0.03A, 0603; Item Num: P09-21344R; LIFECYCLE_PHASE: Active; Lead Free Status: Lead Free; Manufacturer: Wurth Electroniks; Manufacturer Part Num: 150060VS75000; Num Pins: 2; PART_SUBCLASS: LEDS; Part Class: LEDS; RoHS Compliant: RoHS Compliant
J16 = 615008137421_0: CONN MOD JACK 8P8C R/A SHIELDED; Item Num: P23-38806R; Manufacturer: Wurth Elektronik
L9 = INDUCTOR: FIXED IND 4.7UH 850MA 310 mOHM; AGILE_LINK: http://sj-agile9app/Agile/PLMServlet?action=OpenEmailObject&classid=10000&objid=259414331; Item Num: P04-17202R; MFR_LIFECYCLE: Active; Manufacturer: Wurth Elektronik; Manufacturer Part Num: 744028004; PART_SUBCLASS: INDUCTORS
R28 = RESISTOR: RES SMD 1M OHM 1% 1/4W 1206; Item Num: P02-17885R; Manufacturer: Panasonic; Manufacturer Part Num: ERJ-8ENF1004V
R95 = RESISTOR: RES SMD 5.1 OHM 5% 1/10W 0402; Item Num: P02-17895R; Manufacturer: Panasonic; Manufacturer Part Num: ERJ-2GEJ5R1X
R96-R99 R235 R297 R298 = R: RES - 1K OHM, 1/16W, 1%, 0402, SMD; Item Num: P02-14274R; Manufacturer: Vishay; Manufacturer Part Num: CRCW04021K00FKED; Price: 0; RoHS Compliant: Yes
R100 = RES_10K_OHM_5%_1_16W_0402_SMD: RES, 499 OHMS, 1%, 1/16W, 0402; Item Num: P02-14110R; Manufacturer Part Num: ERJ-2RKF4990X
R101 R137 R139 R141 R144-R148 R179 R190 R199 R200 = RES_10K_OHM_5%_1_16W_0402_SMD
R102-R107 R160 R162 = RESISTOR: RES 33 OHM 1/16W 5% 0402 SMD; Altera Part No.: P02-14020R; Item Num: P02-14029R; Manufacturer: Panasonic; Manufacturer Part Num: ERJ-2GEJ330X
R108 R110 = RESISTOR: RES SMD 16K OHM 1% 1/16W 0402; Item Num: P02-17882R; Manufacturer: Vishay Dale; Manufacturer Part Num: CRCW040216K0FKED; Num Pins: 2; Part Class: Resistors; Price: 0; RoHS Compliant: Yes
R109 R112 = RESISTOR: RES - 11K OHM, 1/16W, 1%, 0402 SMD; Item Num: P02-15349R; Manufacturer: Panasonic; Manufacturer Part Num: ERJ-2RKF1102x; Num Pins: 2; Part Class: Resistors; Price: 0; RoHS Compliant: Yes
R114 = RESISTOR: RES - 3.92K OHM, 1/10W, 1%, 0402 SMD; Item Num: P02-17578R; Manufacturer: Panasonic; Manufacturer Part Num: ERJ-2RKF3921X; Num Pins: 2; Part Class: Resistors; Price: 0; RoHS Compliant: Yes
R208-R211 = RESISTOR: RES - 75 OHM 1/10W 5% 0603; Item Num: P02-16288R; Manufacturer: Panasonic; Manufacturer Part Num: ERJ-3GEYJ750V; Price: 0; RoHS Compliant: Yes
R135 R138 R140 R142 R143 R240-R242 = R: RES, 390 Ohms, 5%, 1/16W, 0402; Item Num: P02-14109R; Manufacturer: Panasonic; Manufacturer Part Num: ERJ-2GEJ391X; Num Pins: 2; Part Class: Resistors; Price: 0; RoHS Compliant: Yes
R275 R307 = RESISTOR: RES - 0 OHM, 5% 0603 1/10W; Item Num: P02-14007R; Manufacturer: Panasonic; Manufacturer Part Num: ERJ-3GEY0R00V
TP5-TP7 TP12-TP22 = VIA_1
U14 = PEF7071: XWAY PHY11G SINGLE PORT GIGABIT ETHERNET PHY; Item Num: P01-18118R; Manufacturer: Intel; Manufacturer Part Num: PEF7071VV16
U28 = 749020010A: TRANSFORMER LAN 10/100/1000 SMD; Item Num: P16-29174R; Manufacturer: Wurth Elektronik
Y2 = XTAL_25MHz_30PPM_18pF_mini
C30 = Cap_0.47UF_-20%+80%_10V_0402
F1-F3 = FUSE: PTC RESTTBLE 1.0A 6V CHIP 0805; Item Num: P12-27297R; Manufacturer: Bel Fuse Inc.; Manufacturer Part Num: 0ZCK0100FF2E; RoHS Compliant: Yes
J4 J7 = 61300811821: 1x8 2.54mm Socket Header; Item Num: P23-38798R; Manufacturer: Wurth Elektronik
J5 = 61300811821_1: 1x10 2.54mm Socket Header; Item Num: P23-38811R; Manufacturer: Wurth Elektronik
J6 = 61300811821_0: 1x6 2.54mm Socket Header; Item Num: P23-38810R; Manufacturer: Wurth Elektronik
J18 = hdr2x3_87227: 2X3 2.54MM VERTICAL HEADER; ASSY: DNI; Item Num: P23-38813R; Manufacturer: Wurth Elektronik
L5 L10 L12 L16 = IND_Ferrite_0603_3A_30_Ohms: IND - SMD EMI FILTERS/CHIP FERRITE BEAD, 180-OHM @ 100MHZ, 0.09-OHM DCR, 1.5A, 0603; Item Num: P04-17069R; Manufacturer Part Num: 742792624
R152 R155 R157 R263 R264 R280 = RESISTOR: RES ZERO OHM 1/16W 5% 0402 SMD; Item Num: P02-14020R; Lead Free Status: No; Manufacturer: Panasonic; Manufacturer Part Num: ERJ-2GE0R00X; Num Pins: 2; Part Class: Resistors; RoHS Compliant: Yes
R295 = RESISTOR: RES ZERO OHM 1/16W 5% 0402 SMD; Altera Part No.: P02-14020R; Item Num: P02-14020R; Lead Free Status: No; Manufacturer: Panasonic; Manufacturer Part Num: ERJ-2GE0R00X; Num Pins: 2; Part Class: RESISTORS; Price: 0; RoHS Compliant: Yes; Tolerance: 5%
R300 R308 R309 = RESISTOR: RES ZERO OHM 1/16W 5% 0402 SMD; Item Num: P02-14020R; Lead Free Status: No; Manufacturer: Panasonic; Manufacturer Part Num: ERJ-2GE0R00X; Num Pins: 2; Part Class: Resistors; Price: 0; RoHS Compliant: Yes
U12 = REF3125_1: IC - VREF SERIES 3.0V SOT23-3; Item Num: P01-18073R; Manufacturer: Texas Instruments, Inc.; Manufacturer Part Num: REF3130AIDBZTG4
J8 = 2x6_PMOD: CONN - HEADER 2X6CONN HEADER - 12 POS, 2.54MM ANGLED DUAL SOCKET HEADER WR-PHD, 0.1", TH LEADS 0.1", LEAD LENGTH 0.230"; Item Num: P23-38635R; Manufacturer: Wurth Elektronik; Manufacturer Part Num: 613012243121
J10 = 2x10_0: CONN - CONN HEADER VERT DUAL 40POS 2.54 SHROUDED; Item Num: P23-38816R; Manufacturer: Wurth Elektronik; Manufacturer Part Num: 61204021621
R116-R123 = RESISTOR: RES,200 OHMS,1.0%,1/16W,0402; Item Num: P02-10716R; Lead Free Status: Yes; Manufacturer: Panasonic; Manufacturer Part Num: ERJ-2RKF2000X; Num Pins: 2; Part Class: Resistors; Price: 0; RoHS Compliant: Yes
R265 R266 R269 R270 = RESISTOR: RES,2.00K OHMS,1.0%,1/16W,0402; Item Num: P02-11376R; Manufacturer: Panasonic; Manufacturer Part Num: ERJ-2RKF2001X; Price: 0
U15 U16 = 824013: DIODE - TVS DIODE, HIGH SPEED SERIES, 3.3VWM 6VC SOT23; Item Num: P08-20832R; Manufacturer: Wurth Elektronik
D4 = LED: LED - BLUE, VF = 3.2V, IF = 0.03A, 0603; Item Num: P09-21352R; Lead Free Status: No; Manufacturer: Wurth Elektronik; Manufacturer Part Num: 150060BS75000
D5 = LED_WURTH_1: LED -YELLOW, VF=2V, IF=0.03A, 0603; Item Num: P09-21346R; Manufacturer: Wurth Electroniks; Manufacturer Part Num: 150060YS75000
Q5 = PWRMOSFET_EN_GSD_0: IC, MOSFET, N-Channel, 20V; Item Num: P18-31002R; Manufacturer: Fairchild Semiconductor
S1-S6 = TS-A02SA-2-S100_0: SWITCH - PUSH BUTTON 6.0X3.5MM SND; Item Num: P23-38485R; Lead Free Status: Yes; Manufacturer: Wurth Elektroniks; Manufacturer Part Num: 434121043816; Num Pins: 2; Part Class: Switches; RoHS Compliant: Yes
SW1 = SPST4: SWITCHES - 4 POS, 8 PIN, Ultra-mini SMT Half-pitch Slider DIP Switch; AGILE_LINK: http://sj-agile9app/Agile/PLMServlet?action=OpenEmailObject&classid=10000&objid=258073635; Item Num: P11-24098R; LIFECYCLE_PHASE: Preliminary; Lead Free Status: Not Lead Free; MFR_LIFECYCLE: Active; Manufacturer: Wurth Electronik; Manufacturer Part Num: 416131160804; Num Pins: 8; PART_SUBCLASS: SWITCHES; RoHS Compliant: RoHS Compliant
C66 C73 = Cap_18PF_5%_50V_0402: Manufacturer: Murata; Manufacturer Part Num: GRM1555C1H180JA01D
U20 = Si510-DualCMOS_0: OSC - 50MHZ, +/-30PPM, 3.3V, DUAL CMOS (IN PHASE), CRYSTAL OSCILLATOR, SMD; Item Num: P13-27235R; Manufacturer: Silicon Labs
U31 = Si5351A-B-GT: IC - SI5351A, PROGRAMMABLE CMOS CLOCK, 125M, 100M, 25M DEFAULTS, I2C 0X60, 10-MSOP; Item Num: P01-18143R; Manufacturer: Silicon Labs
Y3 = XTAL_25MHz_30PPM_18pF_mini: CRYSTAL 25.000 MHZ 5.0X3.2MM 50PPM; Item Num: P07-19608R; Manufacturer: Epson; Manufacturer Part Num: FA-238 25.0000MB-K3
C76 C85 C86 C211 = CAP: CAP - CER 47UF, 10V, 20%, X5R, +/-20%, 0805; Item Num: P03-17686R; Manufacturer: TDK Electronics; Manufacturer Part Num: C2012X5R1A476M125AC
C201 = CAP: CAP - CERAMIC, 0.47UF, 15%, 16VDC, 0603, X7R; Item Num: P03-15108R; Manufacturer: Murata; Manufacturer Part Num: GRM188R61C474KA93B
D20 = ZC2800E_SOT: DIODE SCHOTTKY 40V 2A POWERDI123 DFSL240; Item Num: P08-20853R; Manufacturer: Diodes Inc.; Manufacturer Part Num: DFLS240-7
D28 = ZENERDIODE_2: DIODE ZENER 5.1V 0.35W SOT-23; Item Num: P08-20660R; Manufacturer: Diodes Inc.; Manufacturer Part Num: BZX84C5V1
D41 = D-SCHOTTKY_0: DIODE SCHOTTKY 30V 5A SOD128; Manufacturer: Nexperia; item Num: P08-20851R
J12 = Jack-DC: Power Barrel Connector Jack 2.10mm ID (0.083"), 5.50mm OD (0.217") Through Hole, Right Angle; Item Num: P23-38807R; Manufacturer: Wurth Elektronik; Manufacturer Part Num: 694106301002
Q15 Q30 = DMP3098L: 20V P-CHANNEL ENHANCEMENT MODE MOSFET; Item Num: P18-31457R; Manufacturer: Diodes Inc; Manufacturer Part Num: DMG2305UX-7
Q29 = MMBT3906_SOT_0: 40 PNP SMALL SIGNAL TRANSISTOR IN SOT323 PACKAGE; Item Num: P05-18789R; Manufacturer: Diodes; Part Number: DIODES INC. MMST3906-7-F
R164 R165 R296 = RESISTOR: RES SMD 0.0 OHM JUMPER 1/2W 0805; Item Num: P02-17898R; Manufacturer: Vishay Dale; Manufacturer Part Num: CRCW08050000Z0EAHP
R173 = RESISTOR: RES 1K OHM 1/4W 5% 0805 SMD; Item Num: P02-17649R; Manufacturer: Panasonic; Manufacturer Part Num: ERJ-T06J102V
R289 = R: RES - 300 OHM, 0402,  0.0632W, 1%, SMD; Item Num: P02-14162R; Manufacturer: Vishay; Manufacturer Part Num: CRCW0402300RFKED; Num Pins: 2; Part Class: Resistors; Price: 0; RoHS Compliant: Yes
R290 = RES_10K_OHM_5%_1_16W_0402_SMD: RES - 1K OHM, 1/16W, 1%, 0402, SMD; Item Num: P02-14274R; Manufacturer: Vishay; Manufacturer Part Num: CRCW04021K00FKED
R291 = RES_10K_OHM_5%_1_16W_0402_SMD: RES 10K OHM 1/16W 5% 0402 SMD; Item Num: P02-14023R; Manufacturer Part Num: ERJ-2RKF4991X
R292 = RESISTOR: RES 10K OHM 1/16W 5% 0402 SMD; Item Num: P02-14023R; Manufacturer: Panasonic; Manufacturer Part Num: ERJ-2GEJ103X; Price: 0
R294 R299 = RES_10_OHM_1.0%_1_16W_0402: RES, 10 OHMS, 1.0%, 1/10W, 0402
C83 C96 = Cap_0.1UF_+_-10%_10V_0402: CAP - CER 22UF, 10V, 20%, X5R, 0805; Item Num: P03-17685R; Manufacturer: TDK Electronics; Manufacturer Part Num: C2012X5R1A226M085AC
C84 C97 = Cap_0.1UF_+_-10%_10V_0402: CAP - CER 8.2PF 25V NP0 0402; Item Num: P03-17710R; Manufacturer: Murata; Manufacturer Part Num: GRM1555C1E8R2DA01D
C87 C89 C100 C102 C111 C112 = CAP_1.0UF_10%_10V_0402: Manufacturer: Murata; Manufacturer Part Num: GRM155R61A105KE15D
C98 C99 = Cap_0.1UF_+_-10%_10V_0402: CAP - CER, 22UF, 6.3V, +/-10%, X5R, 0805 SMD; Item Num: P03-16292R; Manufacturer: Taiyo Yuden; Manufacturer Part Num: JMK212BJ226KG-T
C103 C104 = CAP: CAP - CER 5PF, 50V, +/-0.25PF, NP0, 0402; Item Num: P03-17675R; Manufacturer: Murata; Manufacturer Part Num: GRM1555C1H5R0CA01D; Price: 0
C105 C106 C165 C166 = Cap_0.1UF_+_-10%_10V_0402: CAP - CER 4.7UF, 25V, 10%, X5R, 0603; Item Num: P03-17677R; Manufacturer: Murata; Manufacturer Part Num: GRM188R61E475KE11D
C107-C110 = CAP: CAP - CERAMIC, 10UF, 10%, 10VDC, 0805, X5R; Item Num: P03-15116R; Manufacturer: Murata; Manufacturer Part Num: GRM21BR61A106KE19L; RoHS Compliant: RoHS Compliant
R178 R189 = RESISTOR: RES,100K OHMS,1.0%,1/16W,0402; Item Num: P02-11386R; Manufacturer: Panasonic; Manufacturer Part Num: ERJ-2RKF1003X; Price: 0
R180 R191 = RESISTOR: RES 348K OHM 1/10W 1% 0402 SMD; Item Num: P02-17553R; Manufacturer: Panasonic; Manufacturer Part Num: ERJ-2RKF3483X
R181 = RESISTOR: RES, 76.8K OHM, 1/16W 1% 0402 SMD; Item Num: P02-17654R; Manufacturer: Vishay; Manufacturer Part Num: CRCW040276K8FKED
R192 = RESISTOR: RES - 340K OHM, 1/10W, 1%, 0402 SMD; Item Num: P02-17547R; Manufacturer: Panasonic; Manufacturer Part Num: ERJ-2RKF3403X
R197 R198 R201 = RESISTOR: RES ZERO OHM 1/16W 5% 0402 SMD; Item Num: P02-14020R; Manufacturer: Panasonic; Manufacturer Part Num: ERJ-2GE0R00X
U23 = EN5329_5339QI_0: REG - 3A LOW PROFILE SYNC BUCK DC-DC, VIN 2.4 - 5.5V, 24-QFN; Item Num: P05-18753R; Manufacturer: Enpirion; Part Class: Regulators; RoHS Compliant: Yes
U25 = EN5329_5339QI_0: 2A LOW PROFILE SYNC BUCK DC-DC, VIN 2.4 - 5.5V, 24-QFN; Item Num: P05-18754R; Manufacturer: Enpirion; Part Class: Regulators; RoHS Compliant: Yes
U26 U27 = EP5358xUI: REGULATOR - DC/DC  1.8-3.3V 2W; Item Num: P05-18741R; Manufacturer: Enpirion; Part Class: Regulators; RoHS Compliant: Yes

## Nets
1.8V_VSENSE: C104.2 R197.2 U26.5(VSENSE)
2.5V_VSENSE: C103.2 R198.2 U27.5(VSENSE)
3.3V_SI510: C74.2 L12.2 U20.2(OE) U20.6(VDD)
5V_DCIN: D41.2 J12.1 R164.1 R300.1
GND: C44.2 C45.1 C46.2 C47.2 C48.2 C49.2 C50.1 C51.1 C52.1 C53.2 C54.1 C55.1 C56.1 C57.1 C58.1 C59.2 C60.1 C61.1 C62.1 C63.2 C64.1 C65.1 C66.1 C67.1 C72.1 C73.1 C74.1 C76.2 C83.2 C85.2 C86.2 C87.2 C88.1 C89.2 C96.2 C98.2 C99.2 C100.2 C101.1 C102.2 C105.2 C106.2 C107.2 C108.2 C109.2 C110.2 C111.2 C112.2 C113.1 C114.1 C160.2 C161.2 C162.2 C163.2 C164.2 C165.2 C166.2 C204.2 C205.2 C206.2 C207.2 C208.2 C209.2 C211.2 D28.1(ANODE) J4.6 J4.7 J5.7 J8.5 J8.11 J10.12 J10.30 J12.2 J12.3 J18.6 Q5.2(SOURCE) R28.1 R101.1 R108.1 R109.1 R110.1 R112.1 R114.1 R173.2 R181.1 R201.2 R240.1 R241.1 R242.1 R291.2 R298.2 R309.1 S1.1 S2.1 S3.1 S4.1 S5.1 S6.1 SW1.1(A1) SW1.2(A2) SW1.3(A3) SW1.4(A4) TP12.1(TP) TP13.1(TP) TP14.1(TP) TP15.1(TP) TP16.1(TP) TP17.1(TP) U14.49(EPAD) U15.2(GND) U16.2(GND) U20.3(GND) U23.2(PGND) U23.3(PGND) U23.8(PGND) U23.9(PGND) U23.15(AGND) U23.25(PGND) U23.26(PGND) U25.2(PGND) U25.3(PGND) U25.8(PGND) U25.9(PGND) U25.15(AGND) U25.25(PGND) U25.26(PGND) U26.2(PGND) U26.3(PGND) U26.6(AGND) U27.2(PGND) U27.3(PGND) U27.6(AGND) U27.10(VS1) U27.11(VS0) U31.8(GND) Y2.2 Y2.4 Y3.2 Y3.4 ; also on sheet 4 5 6 7 8 9 10
GND_EARTH_ETH: C159.2 C164.1 J16.13(CGND1) J16.14(CGND2) R28.2
VCC_1.2V: C97.1 C98.1 C99.1 C100.1 R191.2 TP20.1(TP) U25.4(VOUT) U25.5(VOUT) U25.6(VOUT) U25.7(VOUT) ; also on sheet 6 9
VCC_1.2V_EN: C101.2 R190.1 U25.18(ENABLE)
VCC_1.2V_FB: C97.2 R191.1 R192.2 U25.14(VFB)
VCC_1.2V_PG: R189.2 U25.17(POK) ; also on sheet 8
VCC_1.8V: C104.1 C107.1 C108.1 C112.1 R197.1 TP22.1(TP) U26.7(VOUT) U26.8(VOUT) ; also on sheet 6 10
VCC_1.8V_EN: C114.2 R199.1 U26.12(ENABLE)
VCC_2.5V: C103.1 C109.1 C110.1 C111.1 R198.1 TP21.1(TP) U27.7(VOUT) U27.8(VOUT) ; also on sheet 8 9
VCC_2.5V_EN: C113.2 R200.1 U27.12(ENABLE)
VCC_3.3V: C84.1 C85.1 C86.1 C87.1 J4.4 J8.6 J8.12 J10.29 L10.1 L12.1 L16.2 R135.1 R137.2 R138.1 R139.2 R140.1 R141.2 R142.1 R143.1 R144.2 R145.2 R146.2 R147.2 R148.2 R178.1 R180.2 R189.1 R265.2 R266.2 R269.2 R270.2 R280.1 R307.1 TP19.1(TP) U15.5(VDD) U16.5(VDD) U23.4(VOUT) U23.5(VOUT) U23.6(VOUT) U23.7(VOUT) ; also on sheet 4 7 8 9
VCC_3.3V_EN: C88.2 R179.1 U23.18(ENABLE)
VCC_3.3V_FB: C84.2 R180.1 R181.2 U23.14(VFB)
VCC_3.3V_PG: R178.2 U23.17(POK) ; also on sheet 8
VCC_5V: C76.1 C83.1 C89.1 C96.1 C102.1 C105.1 C106.1 C165.1 C166.1 C200.2 C203.1 F1.1 F2.1 F3.1 L5.1 Q15.D R173.1 R179.2 R190.2 R199.2 R200.2 R235.1 R296.2 TP18.1(TP) U23.10(TST2) U23.11(TST1) U23.12(TST0) U23.16(AVIN) U23.19(PVIN) U23.20(PVIN) U25.10(TST2) U25.11(TST1) U25.12(TST0) U25.16(AVIN) U25.19(PVIN) U25.20(PVIN) U26.9(VS2) U26.10(VS1) U26.11(VS0) U26.13(AVIN) U26.14(PVIN) U27.9(VS2) U27.13(AVIN) U27.14(PVIN)
VCC_5V_AR1: F2.2 J4.5 R275.2
VCC_5V_AR2: F3.2 J18.2
VCC_5V_GPIO: F1.2 J10.11
VCC_5V_IN: C201.1 C203.2 C210.2 C211.1 D20.1(CATHODE) D41.1 Q15.S Q29.2(E) Q30.S R164.2 R165.2 R289.1 R292.1 R296.1
A_GND: C30.2 C31.2 U12.3(GND) ; also on sheet 9
ANA_VREF: J5.8 R308.1
ARDUINO_ANA0: J6.1 ; also on sheet 9
ARDUINO_ANA1: J6.2 ; also on sheet 9
ARDUINO_ANA2: J6.3 ; also on sheet 9
ARDUINO_ANA3: J6.4 ; also on sheet 9
ARDUINO_ANA4: J6.5 ; also on sheet 9
ARDUINO_ANA5: J6.6 ; also on sheet 9
ARDUINO_IO0: J7.1 ; also on sheet 4
ARDUINO_IO1: J7.2 ; also on sheet 4
ARDUINO_IO2: J7.3 ; also on sheet 4
ARDUINO_IO3: J7.4 ; also on sheet 4
ARDUINO_IO4: J7.5 ; also on sheet 4
ARDUINO_IO5: J7.6 ; also on sheet 4
ARDUINO_IO6: J7.7 ; also on sheet 4
ARDUINO_IO7: J7.8 ; also on sheet 4
ARDUINO_IO8: J5.1 ; also on sheet 4
ARDUINO_IO9: J5.2 ; also on sheet 4
ARDUINO_IO10: J5.3 ; also on sheet 4
ARDUINO_IO11: J5.4 J18.4 ; also on sheet 4
ARDUINO_IO12: J5.5 J18.1 ; also on sheet 4
ARDUINO_IO13: J5.6 J18.3 ; also on sheet 4
ARDUINO_RSTn: J4.3 J18.5 ; also on sheet 4
ARDUINO_SCL: J5.10 ; also on sheet 4
ARDUINO_SDA: J5.9 ; also on sheet 4
C10_CLK50M: R162.2 ; also on sheet 4
C10_CLK50M_R: R162.1 U20.5(CLKn/2)
C10_CLK_ADJ: R155.2 ; also on sheet 5
C10_NCONFIG: C205.1 S1.2 ; also on sheet 4
C10_RESETn: C204.1 S2.2 ; also on sheet 5
ENET_CLK_125M: R152.2 ; also on sheet 4
ENET_INT: R97.1 U14.47(MDINT) ; also on sheet 5
ENET_LED0: C55.2 D10.1(ANODE) R109.2 U14.24(LED0)
ENET_LED1: C56.2 D11.1(ANODE) R112.2 U14.23(LED1)
ENET_LED2: C65.2 D12.1(ANODE) R114.2 U14.22(LED2)
ENET_MDC: R297.1 U14.41(MDC) ; also on sheet 5
ENET_MDIO: R98.1 U14.42(MDIO) ; also on sheet 5
ENET_REGO: L9.2 R95.1 U14.39(REGO)
ENET_RG_RXCLK: R102.1 ; also on sheet 5
ENET_RG_RXCTL: R103.1 ; also on sheet 5
ENET_RG_RXD0: R104.1 ; also on sheet 5
ENET_RG_RXD1: R105.1 ; also on sheet 5
ENET_RG_RXD2: R106.1 ; also on sheet 5
ENET_RG_RXD3: R107.1 ; also on sheet 5
ENET_RG_TXCLK: U14.9(TX_CLK) ; also on sheet 5
ENET_RG_TXCTL: U14.15(TX_CTL) ; also on sheet 5
ENET_RG_TXD0: U14.14(TXD0) ; also on sheet 5
ENET_RG_TXD1: U14.12(TXD1) ; also on sheet 5
ENET_RG_TXD2: U14.11(TXD2) ; also on sheet 5
ENET_RG_TXD3: U14.10(TXD3) ; also on sheet 5
ENET_RSTn: C54.2 R96.1 U14.16(RSTn) ; also on sheet 5
ENET_TCK: R99.1 U14.19(TCK)
ENET_TDI: TP6.1(TP) U14.18(TDI)
ENET_TDO: TP5.1(TP) U14.21(TDO)
ENET_TMS: TP7.1(TP) U14.20(TMS)
ENET_VDD_1V: C45.2 C46.1 C48.1 C49.1 C50.2 C51.2 C52.2 L9.1 U14.8(VDDC1) U14.13(VDDC3) U14.17(VDDL) U14.40(VDDC2)
ENET_VDD_3.3V: C57.2 C58.2 C59.1 C60.2 C61.2 C62.2 C63.1 C64.2 R96.2 R97.2 R98.2 R99.2 R100.1 R297.2 R307.2 U14.2(VDDP1) U14.7(VDDP2) U14.25(VDDH1) U14.30(VDDH2) U14.35(VDDH3) U14.38(VDDR) U14.45(VDDP3)
ENET_XTAL1: C44.1 U14.36(XTAL1) Y2.3
ENET_XTAL2: C53.1 U14.37(XTAL2) Y2.1
EXT_VREF: R295.2 ; also on sheet 9
EXT_VREF_AR: R308.2 ; also on sheet 9
GPIO0: J10.1 ; also on sheet 5
GPIO1: J10.2 ; also on sheet 5
GPIO2: J10.3 ; also on sheet 5
GPIO3: J10.4 ; also on sheet 5
GPIO4: J10.5 ; also on sheet 5
GPIO5: J10.6 ; also on sheet 5
GPIO6: J10.7 ; also on sheet 5
GPIO7: J10.8 ; also on sheet 5
GPIO8: J10.9 ; also on sheet 5
GPIO9: J10.10 ; also on sheet 5
GPIO10: J10.13 ; also on sheet 4
GPIO11: J10.14 ; also on sheet 4
GPIO12: J10.15 ; also on sheet 4
GPIO13: J10.16 ; also on sheet 4
GPIO14: J10.17 ; also on sheet 4
GPIO15: J10.18 ; also on sheet 4
GPIO16: J10.19 ; also on sheet 4
GPIO17: J10.20 ; also on sheet 4
GPIO18: J10.21 ; also on sheet 4
GPIO19: J10.22 ; also on sheet 4
GPIO20: J10.23 ; also on sheet 4
GPIO21: J10.24 ; also on sheet 4
GPIO22: J10.25 ; also on sheet 4
GPIO23: J10.26 ; also on sheet 4
GPIO24: J10.27 ; also on sheet 4
GPIO25: J10.28 ; also on sheet 4
GPIO26: J10.31 ; also on sheet 4
GPIO27: J10.32 ; also on sheet 4
GPIO28: J10.33 ; also on sheet 4
GPIO29: J10.34 ; also on sheet 4
GPIO30: J10.35 ; also on sheet 4
GPIO31: J10.36 ; also on sheet 4
GPIO32: J10.37 ; also on sheet 4
GPIO33: J10.38 ; also on sheet 4
GPIO34: J10.39 ; also on sheet 4
GPIO35: J10.40 ; also on sheet 4
HBUS_CLK_50M: R157.2 ; also on sheet 5
IOREF: J4.2 R280.2
M10_CLK50M: R160.2 ; also on sheet 7
M10_CLK50M_R: R160.1 U20.4(CLKp/1)
MX1+: J16.1(1+) U28.13(MX4-)
MX1-: J16.2(1-) U28.14(MX4+)
MX2+: J16.3(2+) U28.16(MX3-)
MX2-: J16.6(2-) U28.17(MX3+)
MX3+: J16.4(3+) U28.19(MX2-)
MX3-: J16.5(3-) U28.20(MX2+)
MX4+: J16.7(4+) U28.22(MX1-)
MX4-: J16.8(4-) U28.23(MX1+)
PMOD_D0: R116.1 ; also on sheet 5
PMOD_D1: R118.1 ; also on sheet 5
PMOD_D2: R120.1 ; also on sheet 5
PMOD_D3: R122.1 ; also on sheet 5
PMOD_D4: R117.2 ; also on sheet 5
PMOD_D5: R119.2 ; also on sheet 5
PMOD_D6: R121.2 ; also on sheet 5
PMOD_D7: R123.2 ; also on sheet 5
PMOD_IO0: J8.1 R116.2 U15.1(IO1)
PMOD_IO1: J8.2 R118.2 U15.3(IO2)
PMOD_IO2: J8.3 R120.2 R270.1 U15.4(IO3)
PMOD_IO3: J8.4 R122.2 R269.1 U15.6(IO4)
PMOD_IO4: J8.7 R117.1 U16.1(IO1)
PMOD_IO5: J8.8 R119.1 U16.3(IO2)
PMOD_IO6: J8.9 R121.1 R265.1 U16.4(IO3)
PMOD_IO7: J8.10 R123.1 R266.1 U16.6(IO4)
PWR_GD_LED: Q5.1(GATE) ; also on sheet 8
REG_PG_LED_R: D4.1(ANODE) R235.2
RG_RXCLK: R102.2 U14.6(RX_CLK)
RG_RXCTL: R103.2 U14.48(RX_CTL)
RG_RXD0: R104.2 U14.5(RXD0)
RG_RXD1: R105.2 U14.4(RXD1)
RG_RXD2: R106.2 U14.3(RXD2)
RG_RXD3: R107.2 U14.1(RXD3)
SYS_CONF_DONE: D5.2(CATHODE) ; also on sheet 7
SYS_CONF_DONE_R: D5.1(ANODE) R135.2
SYS_I2C_SCL: R263.1 ; also on sheet 8
SYS_I2C_SDA: R264.1 ; also on sheet 8
TPIAN: U14.27(TPIAN) U28.11(TD4+)
TPIAP: U14.26(TPIAP) U28.12(TD4-)
TPIBN: U14.29(TPIBN) U28.8(TD3+)
TPIBP: U14.28(TPIBP) U28.9(TD3-)
TPICN: R108.2 U14.32(TPICN) U28.5(TD2+)
TPICP: R110.2 U14.31(TPICP) U28.6(TD2-)
TPIDN: U14.34(TPIDN) U28.2(TD1+)
TPIDP: U14.33(TPIDP) U28.3(TD1-)
USB_5V: D20.2(ANODE) Q30.D R165.1 ; also on sheet 7
USER_DIP0: R147.1 SW1.6(B3) ; also on sheet 5
USER_DIP1: R146.1 SW1.7(B2) ; also on sheet 5
USER_DIP2: R145.1 SW1.8(B1) ; also on sheet 5
USER_LED0: D6.2(CATHODE) ; also on sheet 5
USER_LED0_R: D6.1(ANODE) R138.2
USER_LED1: D7.2(CATHODE) ; also on sheet 5
USER_LED1_R: D7.1(ANODE) R140.2
USER_LED2: D8.2(CATHODE) ; also on sheet 5
USER_LED2_R: D8.1(ANODE) R142.2
USER_LED3: D9.2(CATHODE) ; also on sheet 5
USER_LED3_R: D9.1(ANODE) R143.2
USER_PB0: C206.1 R137.1 S3.2 ; also on sheet 5
USER_PB1: C207.1 R139.1 S4.2 ; also on sheet 5
USER_PB2: C208.1 R141.1 S5.2 ; also on sheet 5
USER_PB3: C209.1 R144.1 S6.2 ; also on sheet 5
VTAP_BYPASSn: R148.1 SW1.5(B4) ; also on sheet 8
XA: C66.2 U31.2(XA) Y3.3
XB: C73.2 U31.3(XB) Y3.1
N16666559: C47.1 R95.2
N16670783: R100.2 U14.43(SCL)
N16807169: R101.2 U14.44(SDA)
N16986323: R208.1 U28.15(MCT4)
N16986325: R209.1 U28.18(MCT3)
N16986327: R210.1 U28.21(MCT2)
N16986329: R211.1 U28.24(MCT1)
N16986355: C159.1 R208.2 R209.2 R210.2 R211.2
N17050331: C30.1 L5.2 U12.1(VIN)
N17106026: D10.2(CATHODE) R240.2
N17106333: D11.2(CATHODE) R241.2
N17106465: D12.2(CATHODE) R242.2
N17225816: R192.1 R201.1
N17241873: J4.8 R275.1
N17244926: C160.1 U28.10(TCT4)
N17244940: C161.1 U28.7(TCT3)
N17244954: C162.1 U28.4(TCT2)
N17244968: C163.1 U28.1(TCT1)
N17285342: C67.2 L10.2 U31.1(VDD)
N17285440: R264.2 U31.5(SDA)
N17285442: R263.2 U31.4(SCL)
N17285490: R152.1 U31.10(CLK0)
N17285492: R155.1 U31.9(CLK1)
N17285494: R157.1 U31.6(CLK2)
N17285521: C72.2 L16.1 U31.7(VDDO)
N17472668: D28.3(CATHODE) R289.2 R290.2
N17473523: C200.1 C201.2 Q29.3(C) R291.1 R292.2 R294.2
N17473566: Q29.1(B) R290.1
N17490351: Q15.G R294.1
N17512425: C31.1 R295.1 U12.2(VOUT)
N17554452: C210.1 R298.1 R299.2 R300.2
N17555511: Q30.G R299.1
N17689344: D4.2(CATHODE) Q5.3(DRAIN) R309.2

Not connected (* = marked no-connect by the designer): D28 2(NC)*; J4 1*; U14 46(CLKOUT)*; U20 1(NC)*; U23 1(NC(SW)0)* 13(NC)* 21(NC(SW)1)* 22(NC(SW)2)* 23(NC(SW)3)* 24(NC(SW)4)*; U25 1(NC(SW)0)* 13(NC)* 21(NC(SW)1)* 22(NC(SW)2)* 23(NC(SW)3)* 24(NC(SW)4)*; U26 1(NC1)* 4(VFB/NC4)* 15(NC15)* 16(NC16)*; U27 1(NC1)* 4(VFB/NC4)* 15(NC15)* 16(NC16)*

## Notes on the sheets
sheet 11
- Ethernet RGMII
- IND 4.7uH 850mA 310mOhm
- Rcal for calibration
- CBV[3]
- CBV[2]
- CBV[1]
- CBV[0]
- Rcfg + Ccfg
- NET
- ON
- OFF
- Blink
- LED0
- ADR[3]
- 0
- ADR[2]
- 0
- ADR[1]
- 0
- ADR[0]
- 0
- 11K+DNI
- NET_LED0
- Link-up
- Link-down
- Traffc
- LED1
- ADR[4]
- 0
- MODE[1]
- 0
- MODE[0]
- 0
- FLOW
- 0
- 11K+DNI
- NET_LED1
- 100Mbps
- Other Status
- N/A
- LED2
- CONF[1]
- 0
- CONF[0]
- 1
- ANEG[1]
- 0
- ANEG[0]
- 0
- 3.92K+DNI
- NET_LED2
- 1000Mbps
- Other Status
- N/A
sheet 12
- Arduino Digital IO
- Arduino Power Output Capability
  3.3V: J4.2, J4.4 100mA Max. total
  5V: J4.5, J18.2 500mA Max. total
  Using external adaptor power input (J12)
- Arduino Analog IO
- Arduino I2C
sheet 13
- PMOD
- PMOD Specification not specified module power consumption but assumed no more than approximately 100mA.
- PMOD
- 2x20 GPIO
- 2x20pin GPIO Header
sheet 14
- POWER LED
- Push Buttons
- Configuration LED
- User LED
- DIP Switches
- ON = 0
- Logic 0 = Vitual JTAG Bypass
  Logic 1 = Vitual JTAG Enable
- OFF = 1
sheet 15
- Si5351A
- 3.3V CMOS
- 3.3V CMOS
- System I2C
- 3.3V CMOS
- Use Clock GUI to Program Si5351A
  Default Prequency:
  CLK0: 125MHz
  CLK1: 100MHz
  CLK2: 50MHz
  I2C Address: 0x60
- Clocks
- 50MHz Oscillator
- 3.3V CMOS
- 3.3V CMOS
sheet 16
- 5V Input Selection, Protection and Control
- 5V DC Input
  ID=2.1mm,OD=5.5mm
sheet 17
- VCC_1.2V (1.2V@2A Max.)
- VCC_1.8V (1.8V@0.6A Max.)
- VCC_2.5V (2.5V@0.6A Max.)
- VCC_3.3V (3.3V@3A Max.)
